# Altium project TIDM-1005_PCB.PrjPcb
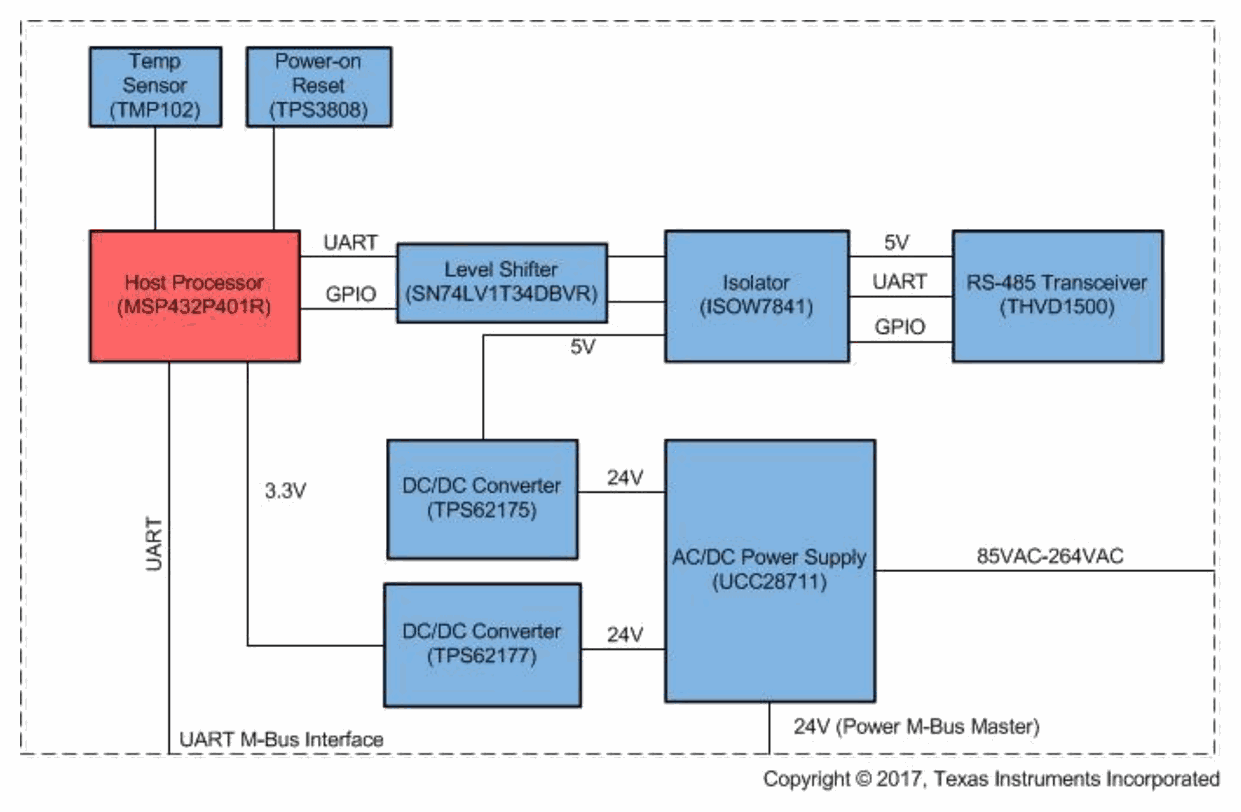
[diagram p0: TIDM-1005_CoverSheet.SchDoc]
CopyrightYear: 2017; PCB_Layout: Wonsoo Kim; PCB_Rev: E1; PRJ_Customer: Public Release; PRJ_Engineer: Wonsoo Kim; PRJ_Number: TIDM-1005; PRJ_Title: TIDM-1005; SCH_Rev: E1; TechSupport: http://www.ti.com/support; TID: TIDM-1005
5 sheets, 160 parts. Net scope: flat (ports and power ports of the same name join across sheets).
Board file: TIDM-1005_PCB.PcbDoc
Sheets:
  TIDM-1005_CoverSheet.SchDoc
  TIDM-1005_1.SchDoc
  TIDM-1005_2.SchDoc
  TIDM-1005_3.SchDoc
  TIDM-1005-EVM_Hardware.SchDoc

## Sheet TIDM-1005_CoverSheet.SchDoc
size 431 x 279 mm; Date: Not shown in title block; ApprovedBy: Not shown in title block; CheckedBy: Not shown in title block; Author: Not shown in title block; CompanyName: Not shown in title block; Engineer: Not shown in title block; Organization: Not shown in title block; Address1: Not shown in title block; Address2: Not shown in title block; Address3: Not shown in title block; Address4: Not shown in title block; DocumentNumber: 1; Revision: Use project parameter SCH_Rev; SheetNumber: 0; SheetTotal: 4; PageSetup: Record=PageOptions¦CenterHorizontal=True¦CenterVertical=True¦PrintScale=1.00¦XCorrection=1.00¦YCorrection=1.00¦PrintKind=0¦BorderSize=5000000¦LeftOffset=0¦BottomOffset=0¦Orientation=2¦PaperLength=1000¦PaperWidth=1000¦Scale=100¦PaperSource=15¦PrintQuality=600¦MediaType=1¦DitherType=10¦PaperKind=Letter¦PrintScaleMode=1

## Sheet TIDM-1005_1.SchDoc
size 431 x 279 mm; Date: Not shown in title block; ApprovedBy: Not shown in title block; CheckedBy: Not shown in title block; Author: Not shown in title block; CompanyName: Not shown in title block; Engineer: Not shown in title block; Organization: Not shown in title block; Address1: Not shown in title block; Address2: Not shown in title block; Address3: Not shown in title block; Address4: Not shown in title block; DocumentNumber: 1; Revision: Use project parameter SCH_Rev; SheetNumber: 1; SheetTotal: 4; PageSetup: Record=PageOptions¦CenterHorizontal=True¦CenterVertical=True¦PrintScale=1.00¦XCorrection=1.00¦YCorrection=1.00¦PrintKind=0¦BorderSize=5000000¦LeftOffset=0¦BottomOffset=0¦Orientation=2¦PaperLength=1000¦PaperWidth=1000¦Scale=100¦PaperSource=15¦PrintQuality=600¦MediaType=1¦DitherType=10¦PaperKind=Letter¦PrintScaleMode=1
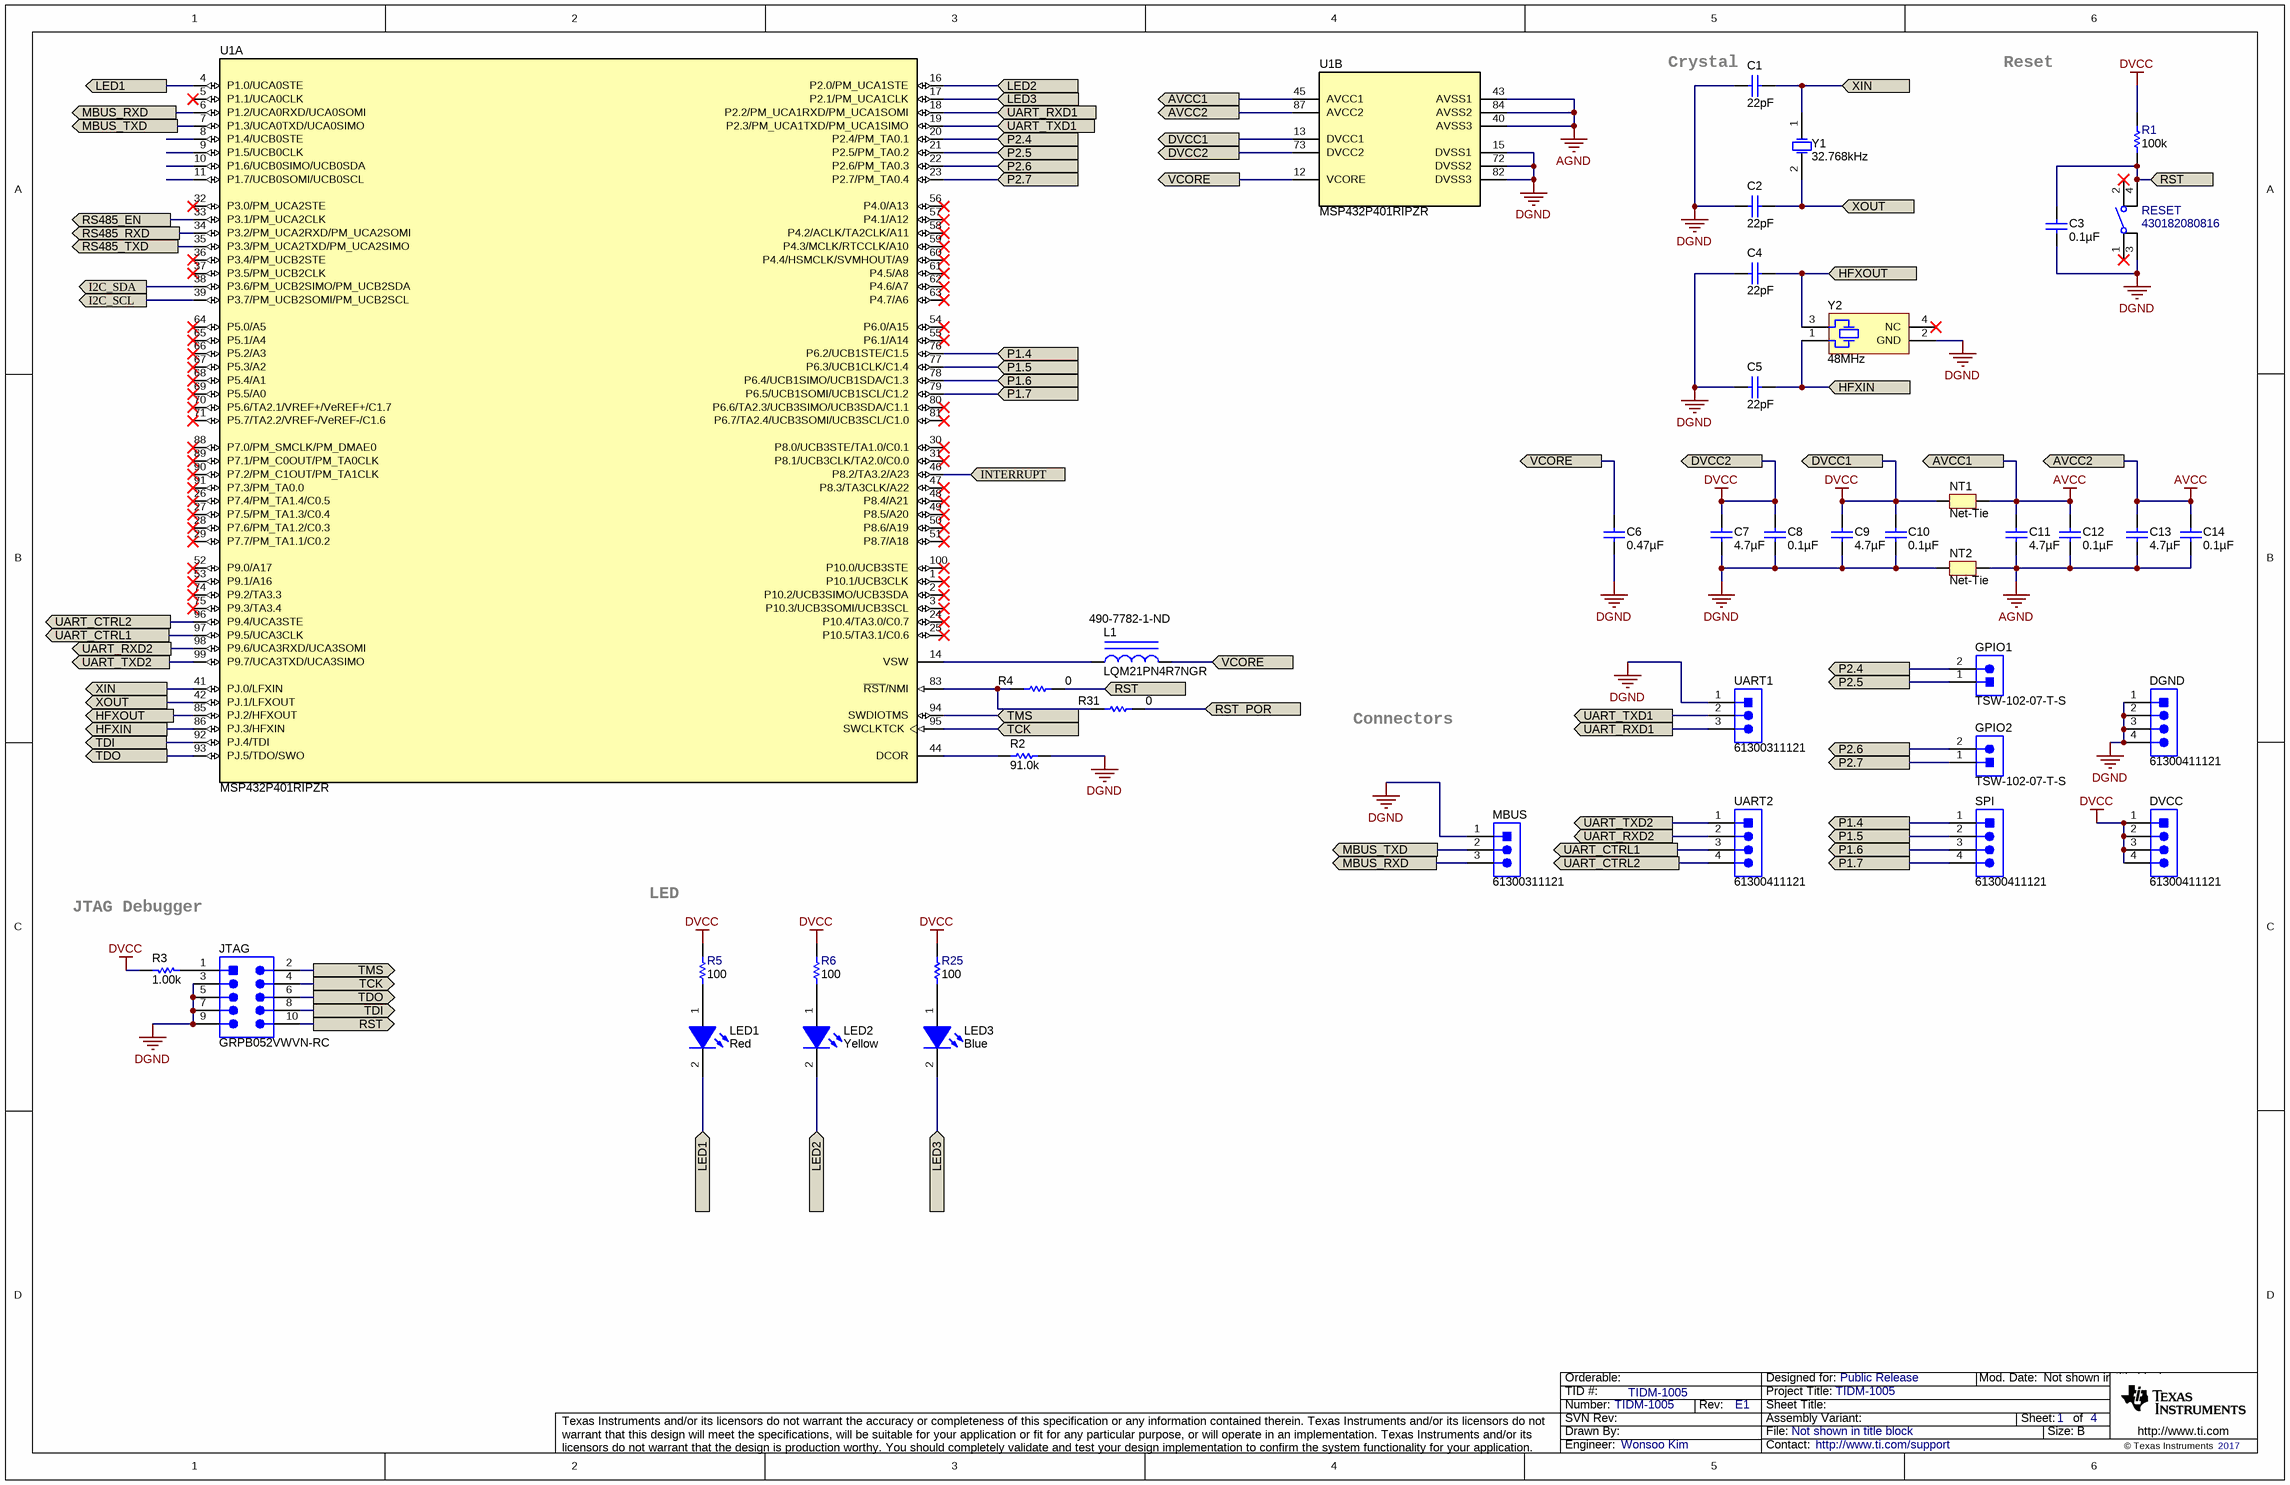
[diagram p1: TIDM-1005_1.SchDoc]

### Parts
C1  ValueDisplayed: 22pF  [0402]  (hidden comment: C1005C0G1H220J050BA)
C2  ValueDisplayed: 22pF  [0402]  (hidden comment: C1005C0G1H220J050BA)
C3  ValueDisplayed: 0.1µF  [0603]  (hidden comment: 06033C104KAT2A)
C4  ValueDisplayed: 22pF  [0402]  (hidden comment: C1005C0G1H220J050BA)
C5  ValueDisplayed: 22pF  [0402]  (hidden comment: C1005C0G1H220J050BA)
C6  ValueDisplayed: 0.47µF  [0603]  (hidden comment: GRM188R71E474KA12D)
C7  ValueDisplayed: 4.7µF  [0603]  (hidden comment: GRM188R6YA475KE15D)
C8  ValueDisplayed: 0.1µF  [0603]  (hidden comment: GCM188R71H104KA57D)
C9  ValueDisplayed: 4.7µF  [0603]  (hidden comment: GRM188R6YA475KE15D)
C10  ValueDisplayed: 0.1µF  [0603]  (hidden comment: GCM188R71H104KA57D)
C11  ValueDisplayed: 4.7µF  [0603]  (hidden comment: GRM188R6YA475KE15D)
C12  ValueDisplayed: 0.1µF  [0603]  (hidden comment: GCM188R71H104KA57D)
C13  ValueDisplayed: 4.7µF  [0603]  (hidden comment: GRM188R6YA475KE15D)
C14  ValueDisplayed: 0.1µF  [0603]  (hidden comment: GCM188R71H104KA57D)
DGND  61300411121  [WURTH_61300411121]
DVCC  61300411121  [WURTH_61300411121]
GPIO1  TSW-102-07-T-S  [Samtec_TSW-102-07-T-S]
GPIO2  TSW-102-07-T-S  [Samtec_TSW-102-07-T-S]
JTAG  GRPB052VWVN-RC  [CONN_GRPB052VWVN-RC]
L1  LQM21PN4R7NGR  Supplier Part Number 4: 490-7782-1-ND  [IND_LQM18P_FH]
LED1  value Red  [LED_LTST-C170_Red]  (hidden comment: LTST-C170KRKT)
LED2  value Yellow  [LED_LTST-C170]  (hidden comment: LTST-C170KSKT)
LED3  value Blue  [LTST-C170TBKT_Blue]  (hidden comment: LTST-C170TBKT)
MBUS  61300311121  [WURTH_61300311121]
NT1  Net-Tie  [Net-Tie_10mil]  (net tie, no BOM)
NT2  Net-Tie  [Net-Tie_10mil]  (net tie, no BOM)
R1  ValueDisplayed: 100k  [0603]  (hidden comment: ERA-3AEB104V)
R2  ValueDisplayed: 91.0k  [0805_HV]  (hidden comment: RG2012P-913-B-T5)
R3  ValueDisplayed: 1.00k  [0603]  (hidden comment: ERJ-3EKF1001V)
R4  value 0  [0603]  (hidden comment: CRCW06030000Z0EA)
R5  ValueDisplayed: 100  [0603]  (hidden comment: ERA-3AEB101V)
R6  ValueDisplayed: 100  [0603]  (hidden comment: ERA-3AEB101V)
R25  ValueDisplayed: 100  [0603]  (hidden comment: ERA-3AEB101V)
R31  value 0  [0603]  (hidden comment: CRCW06030000Z0EA)
RESET  430182080816  [SW_430182080816]
SPI  61300411121  [WURTH_61300411121]
U1  MSP432P401RIPZR  [PZ0100A_N]  (parts A,B of 2)
UART1  61300311121  [WURTH_61300311121]
UART2  61300411121  [WURTH_61300411121]
Y1  Frequency: 32.768kHz  [Epson_FC-135]  (hidden comment: FC-135R 32.7680KA-A3)
Y2  Frequency: 48MHz  [Kyocera_CX2016DB]  (hidden comment: CX2016DB48000H0FLJC1)

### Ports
AVCC1, AVCC2, DVCC1, DVCC2, HFXIN, HFXOUT, I2C_SCL, I2C_SDA, INTERRUPT, LED1, LED2, LED3, MBUS_RXD, MBUS_TXD, P1.4, P1.5, P1.6, P1.7, P2.4, P2.5, P2.6, P2.7, RS485_EN, RS485_RXD, RS485_TXD, RST, RST_POR, TCK, TDI, TDO, TMS, UART_CTRL1, UART_CTRL2, UART_RXD1, UART_RXD2, UART_TXD1, UART_TXD2, VCORE, XIN, XOUT

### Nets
AGND: C11.1 C12.2 C13.1 C14.2 NT2.2 U1.40(AVSS3) U1.43(AVSS1) U1.84(AVSS2)
AVCC: C11.2 C12.1 C13.2 C14.1 NT1.2 U1.45(AVCC1) U1.87(AVCC2) ; port AVCC1, port AVCC2
DGND: C1.1 C2.1 C3.2 C4.1 C5.1 C6.2 C7.1 C8.2 C9.1 C10.2 DGND.1 DGND.2 DGND.3 DGND.4 JTAG.3 JTAG.5 JTAG.7 JTAG.9 MBUS.1 NT2.1 R2.2 RESET.3 U1.15(DVSS1) U1.72(DVSS2) U1.82(DVSS3) UART1.1 Y2.2(GND)
DVCC: C7.2 C8.1 C9.2 C10.1 DVCC.1 DVCC.2 DVCC.3 DVCC.4 NT1.1 R1.2 R3.2 R5.2 R6.2 R25.2 U1.13(DVCC1) U1.73(DVCC2) ; port DVCC1, port DVCC2
HFXIN: C5.2 U1.86(PJ.3/HFXIN) Y2.1 ; port HFXIN
HFXOUT: C4.2 U1.85(PJ.2/HFXOUT) Y2.3 ; port HFXOUT
I2C_SCL: U1.39(P3.7/PM_UCB2SOMI/PM_UCB2SCL) ; port I2C_SCL
I2C_SDA: U1.38(P3.6/PM_UCB2SIMO/PM_UCB2SDA) ; port I2C_SDA
INTERRUPT: U1.46(P8.2/TA3.2/A23) ; port INTERRUPT
LED1: LED1.2(K) U1.4(P1.0/UCA0STE) ; port LED1
LED2: LED2.2(K) U1.16(P2.0/PM_UCA1STE) ; port LED2
LED3: LED3.2(K) U1.17(P2.1/PM_UCA1CLK) ; port LED3
MBUS_RXD: MBUS.3 U1.6(P1.2/UCA0RXD/UCA0SOMI) ; port MBUS_RXD
MBUS_TXD: MBUS.2 U1.7(P1.3/UCA0TXD/UCA0SIMO) ; port MBUS_TXD
P1.4: SPI.1 U1.76(P6.2/UCB1STE/C1.5) ; port P1.4
P1.5: SPI.2 U1.77(P6.3/UCB1CLK/C1.4) ; port P1.5
P1.6: SPI.3 U1.78(P6.4/UCB1SIMO/UCB1SDA/C1.3) ; port P1.6
P1.7: SPI.4 U1.79(P6.5/UCB1SOMI/UCB1SCL/C1.2) ; port P1.7
P2.4: GPIO1.2 U1.20(P2.4/PM_TA0.1) ; port P2.4
P2.5: GPIO1.1 U1.21(P2.5/PM_TA0.2) ; port P2.5
P2.6: GPIO2.2 U1.22(P2.6/PM_TA0.3) ; port P2.6
P2.7: GPIO2.1 U1.23(P2.7/PM_TA0.4) ; port P2.7
RS485_EN: U1.33(P3.1/PM_UCA2CLK) ; port RS485_EN
RS485_RXD: U1.34(P3.2/PM_UCA2RXD/PM_UCA2SOMI) ; port RS485_RXD
RS485_TXD: U1.35(P3.3/PM_UCA2TXD/PM_UCA2SIMO) ; port RS485_TXD
RST: C3.1 JTAG.10 R1.1 R4.1 RESET.4 ; port RST
RST_POR: R31.1 ; port RST_POR
TCK: JTAG.4 U1.95(SWCLKTCK) ; port TCK
TDI: JTAG.8 U1.92(PJ.4/TDI) ; port TDI
TDO: JTAG.6 U1.93(PJ.5/TDO/SWO) ; port TDO
TMS: JTAG.2 U1.94(SWDIOTMS) ; port TMS
UART_CTRL1: U1.97(P9.5/UCA3CLK) UART2.3 ; port UART_CTRL1
UART_CTRL2: U1.96(P9.4/UCA3STE) UART2.4 ; port UART_CTRL2
UART_RXD1: U1.18(P2.2/PM_UCA1RXD/PM_UCA1SOMI) UART1.3 ; port UART_RXD1
UART_RXD2: U1.98(P9.6/UCA3RXD/UCA3SOMI) UART2.2 ; port UART_RXD2
UART_TXD1: U1.19(P2.3/PM_UCA1TXD/PM_UCA1SIMO) UART1.2 ; port UART_TXD1
UART_TXD2: U1.99(P9.7/UCA3TXD/UCA3SIMO) UART2.1 ; port UART_TXD2
VCORE: C6.1 L1.2 U1.12(VCORE) ; port VCORE
XIN: C1.2 U1.41(PJ.0/LFXIN) Y1.1(OSC1) ; port XIN
XOUT: C2.2 U1.42(PJ.1/LFXOUT) Y1.2(OSC2) ; port XOUT
NetJTAG_1: JTAG.1 R3.1
NetL1_1: L1.1 U1.14(VSW)
NetLED1_1: LED1.1(A) R5.1
NetLED2_1: LED2.1(A) R6.1
NetLED3_1: LED3.1(A) R25.1
NetR2_1: R2.1 U1.44(DCOR)
NetR4_2: R4.2 R31.2 U1.83(~{RST}/NMI)

Not connected (* = marked no-connect by the designer): RESET 1* 2*; U1 1(P10.1/UCB3CLK)* 2(P10.2/UCB3SIMO/UCB3SDA)* 3(P10.3/UCB3SOMI/UCB3SCL)* 5(P1.1/UCA0CLK)* 8(P1.4/UCB0STE) 9(P1.5/UCB0CLK) 10(P1.6/UCB0SIMO/UCB0SDA) 11(P1.7/UCB0SOMI/UCB0SCL) 24(P10.4/TA3.0/C0.7)* 25(P10.5/TA3.1/C0.6)* 26(P7.4/PM_TA1.4/C0.5)* 27(P7.5/PM_TA1.3/C0.4)* 28(P7.6/PM_TA1.2/C0.3)* 29(P7.7/PM_TA1.1/C0.2)* 30(P8.0/UCB3STE/TA1.0/C0.1)* 31(P8.1/UCB3CLK/TA2.0/C0.0)* 32(P3.0/PM_UCA2STE)* 36(P3.4/PM_UCB2STE)* 37(P3.5/PM_UCB2CLK)* 47(P8.3/TA3CLK/A22)* 48(P8.4/A21)* 49(P8.5/A20)* 50(P8.6/A19)* 51(P8.7/A18)* 52(P9.0/A17)* 53(P9.1/A16)* 54(P6.0/A15)* 55(P6.1/A14)* 56(P4.0/A13)* 57(P4.1/A12)* 58(P4.2/ACLK/TA2CLK/A11)* 59(P4.3/MCLK/RTCCLK/A10)* 60(P4.4/HSMCLK/SVMHOUT/A9)* 61(P4.5/A8)* 62(P4.6/A7)* 63(P4.7/A6)* 64(P5.0/A5)* 65(P5.1/A4)* 66(P5.2/A3)* 67(P5.3/A2)* 68(P5.4/A1)* 69(P5.5/A0)* 70(P5.6/TA2.1/VREF+/VeREF+/C1.7)* 71(P5.7/TA2.2/VREF-/VeREF-/C1.6)* 74(P9.2/TA3.3)* 75(P9.3/TA3.4)* 80(P6.6/TA2.3/UCB3SIMO/UCB3SDA/C1.1)* 81(P6.7/TA2.4/UCB3SOMI/UCB3SCL/C1.0)* 88(P7.0/PM_SMCLK/PM_DMAE0)* 89(P7.1/PM_C0OUT/PM_TA0CLK)* 90(P7.2/PM_C1OUT/PM_TA1CLK)* 91(P7.3/PM_TA0.0)* 100(P10.0/UCB3STE)*; Y2 4(NC)*

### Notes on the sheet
- (near C1) Crystal
- Reset
- Connectors
- LED
- JTAG Debugger

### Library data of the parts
C1 C2 C4 C5 = C1005C0G1H220J050BA: CAP, CERM, 22 pF, 50 V, +/- 5%, C0G/NP0, 0402; Manufacturer: TDK; Polarized: N; CompType: Capacitor; Value: 22pF; U/M: EA; Cap_F: 0.000000000022; Tolerance_%: 5; Value1: Unknown; VDC_V: 50; Value2: 50V; TaMin_C: -55; TaMax_C: 125; SizeArea_mm2: 0.5; SizeAreaWB_mm2: 3; SizeX_mm: 1; SizeZ_mm: 0.6; AEC Category: Q200
C3 = 06033C104KAT2A: CAP, CERM, 0.1 µF, 25 V, +/- 10%, X7R, 0603; Manufacturer: AVX; Polarized: N; CompType: Capacitor; Value: 0.1uF; U/M: EA; Cap_F: 0.0000001; Tolerance_%: 10; ESR_ohm: 0.05; Value1: 0.05 ohm; VDC_V: 25; Value2: 25V; TaMin_C: -55; TaMax_C: 125
C6 = GRM188R71E474KA12D: CAP, CERM, 0.47 µF, 25 V, +/- 10%, X7R, 0603; Manufacturer: MuRata; Polarized: N; CompType: Capacitor; Value: 0.47uF; U/M: EA; Cap_F: 0.00000047; Tolerance_%: 10; Value1: Unknown; VDC_V: 25; Value2: 25V; TaMin_C: -55; TaMax_C: 125
C7 C9 C11 C13 = GRM188R6YA475KE15D: CAP, CERM, 4.7 µF, 35 V, +/- 10%, X5R, 0603; Manufacturer: MuRata; Polarized: N; CompType: Capacitor; Value: 4.7uF; U/M: EA; Cap_F: 0.0000047; Tolerance_%: 10; Value1: Unknown; VDC_V: 35; Value2: 35V; TaMin_C: -55; TaMax_C: 85; SizeArea_mm2: 1.28; SizeAreaWB_mm2: 4.68; SizeX_mm: 1.6; SizeY_mm: 0.8; SizeZ_mm: 1; AEC Category: Q200
C8 C10 C12 C14 = GCM188R71H104KA57D: CAP, CERM, 0.1 µF, 50 V, +/- 10%, X7R, 0603; Manufacturer: MuRata; Polarized: N; CompType: Capacitor; Value: 0.1uF; U/M: EA; Cap_F: 0.0000001; Tolerance_%: 10; ESR_ohm: 0.02; Value1: 0.02 ohm; VDC_V: 50; Value2: 50V; IRMS_A: 1.84; TaMin_C: -55; TaMax_C: 125
DGND DVCC = 61300411121: Header, 2.54 mm, 4x1, Gold, TH; Manufacturer: Wurth Elektronik; SymbolCreator: a0412235; U/M: EA
GPIO1 GPIO2 = TSW-102-07-T-S: Header, 2.54 mm, 2x1, Tin, TH; Manufacturer: Samtec; SymbolCreator: a0412235; Pitch_mm: 2.54; Gender: Male; Shrouded: N; Row_Count: 1; Current_A: 6.3; Voltage_V: 550; Cert_CSA: Y
JTAG = GRPB052VWVN-RC: Header, 50mil, 5x2, Gold, TH; Manufacturer: Sullins Connector Solutions; SymbolCreator: a0412235; U/M: EA
L1 = LQM21PN1R0MGH: Inductor, Multilayer, Ferrite, 4.7 µH, 2 A, 0.08 ohm, SMD; Manufacturer: MuRata; Value: 4.7uH; Ind_H: 1.0E-6; Imax_A: 2; Irms: 2A @ 40C rise; Isat: 2.1A @ 30% inductance drop; DCR_ohm: 0.08; Value2: 2A; Tolerance_%: ±30%; Current Rating: 800mA; Shielding: Shielded; Frequency - Self Resonant: 30MHz; Frequency - Test: 1MHz
LED1 = LTST-C170KRKT: LED, Red, SMD; Manufacturer: Lite-On; Type: AlInGaP; Vf_V: 2; Value2: 2V; Io_A: 0.02; Value1: W; SizeAreaWB_mm2: 6.75; SizeArea_mm2: 2.5; SizeY_mm: 1.25; SizeZ_mm: 1.2; U/M: EA
LED2 = LTST-C170KSKT: LED, Yellow , SMD; Manufacturer: Lite-On; Type: AlInGaP; Vf_V: 2; Value2: 2V; Io_A: 0.02; Value1: W; SizeAreaWB_mm2: 6.75; SizeArea_mm2: 2.5; SizeY_mm: 1.25; SizeZ_mm: 1.2; U/M: EA
LED3 = LTST-C170TBKT: LED, Blue, SMD; Manufacturer: Lite-On; Type: AlInGaP; Vf_V: 3.3; Value2: 3.3V; Io_A: 0.02; Value1: W; U/M: EA
MBUS UART1 = 61300311121: Header, 2.54 mm, 3x1, Gold, TH; Manufacturer: Wurth Elektronik; SymbolCreator: a0799628
NT1 NT2 = Net-Tie: Single point connection between nets.; SymbolCreator: codlsc
R1 = ERA-3AEB104V: RES, 100 k, 0.1%, 0.1 W, 0603; Manufacturer: Panasonic; CompType: Resistor; Value: 100k; Res_ohm: 100000; Tolerance_%: 0.1; Value2: 0.1W; VDC_V: 75; TempCo: 25 ppm/C; EIA_Code: E192; U/M: EA
R2 = RG2012P-913-B-T5: RES, 91.0 k, 0.1%, 0.125 W, 0805; Manufacturer: Susumu Co Ltd; CompType: Resistor; Value: 91.0k; Res_ohm: 91000; Value_Code: 91k0; Tolerance_%: 0.1; Power_W: 0.125; Value2: 0.125W; VDC_V: 100; TempCo: 25 ppm/C; U/M: EA
R3 = ERJ-3EKF1001V: RES, 1.00 k, 1%, 0.1 W, 0603; Manufacturer: Panasonic; CompType: Resistor; Value: 1.00k; Res_ohm: 1000; Value_Code: 1k00; Tolerance_%: 1; Power_W: 0.1; Value2: 0.1W; VDC_V: 75; TempCo: 100 ppm/C; EIA_Code: E96; U/M: EA
R4 R31 = CRCW06030000Z0EA: RES, 0 ohm, 5%, 0.1W, 0603; Manufacturer: Vishay-Dale; CompType: Resistor; Value_Code: 0000; Tolerance_%: 5; Power_W: 0.1; VDC_V: 75; TempCo: 200 ppm/C; EIA_Code: E24; U/M: EA
R5 R6 R25 = ERA-3AEB101V: RES, 100, 0.1%, 0.1 W, 0603; Manufacturer: Panasonic; CompType: Resistor; Value: 100; Value_Code: 100R; Tolerance_%: 0.1; Value2: 0.1W; VDC_V: 75; TempCo: 25 ppm/C; EIA_Code: E192; U/M: EA
RESET = 430182080816: Switch, Tactile, SPST-NO, 0.05A, 12V, SMD; Manufacturer: Wurth Elektronik; SymbolCreator: Altium; VDC_V: 12; SwitchFunction: Off-Mom; PositionCount: 1; CurrentRating_mA: 50
SPI UART2 = 61300411121: Header, 2.54 mm, 4x1, Gold, TH; Manufacturer: Wurth Elektronik; SymbolCreator: a0412235
U1 = MSP432P401RIPZR: Mixed-Signal Microcontroller, PZ0100A (LQFP-100); Manufacturer: Texas Instruments; SymbolCreator: Altium; SizeArea_mm2: 256; SizeAreaWB_mm2: 324; SizeX_mm: 16; SizeZ_mm: 1.6; CompType: IC; U/M: EA
Y1 = X1A0001410014: Crystal, 32.768 KHz, 12.5 pF, SMD; Manufacturer: Epson; SymbolCreator: a0412235; U/M: EA; TaMin_C: -40; TaMax_C: 85
Y2 = CX2016DB48000H0FLJC1: Crystal, 48MHz, 12pF, SMD; Manufacturer: Kyocera; SymbolCreator: Altium; SizeAreaWB_mm2: 7.8; SizeArea_mm2: 3.2; SizeX_mm: 1.6; SizeY_mm: 2; SizeZ_mm: 0.45; U/M: EA; TaMin_C: -30; TaMax_C: 85; Frequency Stability: ±15ppm

## Sheet TIDM-1005_2.SchDoc
size 431 x 279 mm; Date: Not shown in title block; ApprovedBy: Not shown in title block; CheckedBy: Not shown in title block; Author: Not shown in title block; CompanyName: Not shown in title block; Engineer: Not shown in title block; Organization: Not shown in title block; Address1: Not shown in title block; Address2: Not shown in title block; Address3: Not shown in title block; Address4: Not shown in title block; DocumentNumber: 2; Revision: Use project parameter SCH_Rev; SheetNumber: 2; SheetTotal: 4; PageSetup: Record=PageOptions¦CenterHorizontal=True¦CenterVertical=True¦PrintScale=1.00¦XCorrection=1.00¦YCorrection=1.00¦PrintKind=0¦BorderSize=5000000¦LeftOffset=0¦BottomOffset=0¦Orientation=2¦PaperLength=1000¦PaperWidth=1000¦Scale=100¦PaperSource=15¦PrintQuality=600¦MediaType=1¦DitherType=10¦PaperKind=Letter¦PrintScaleMode=1
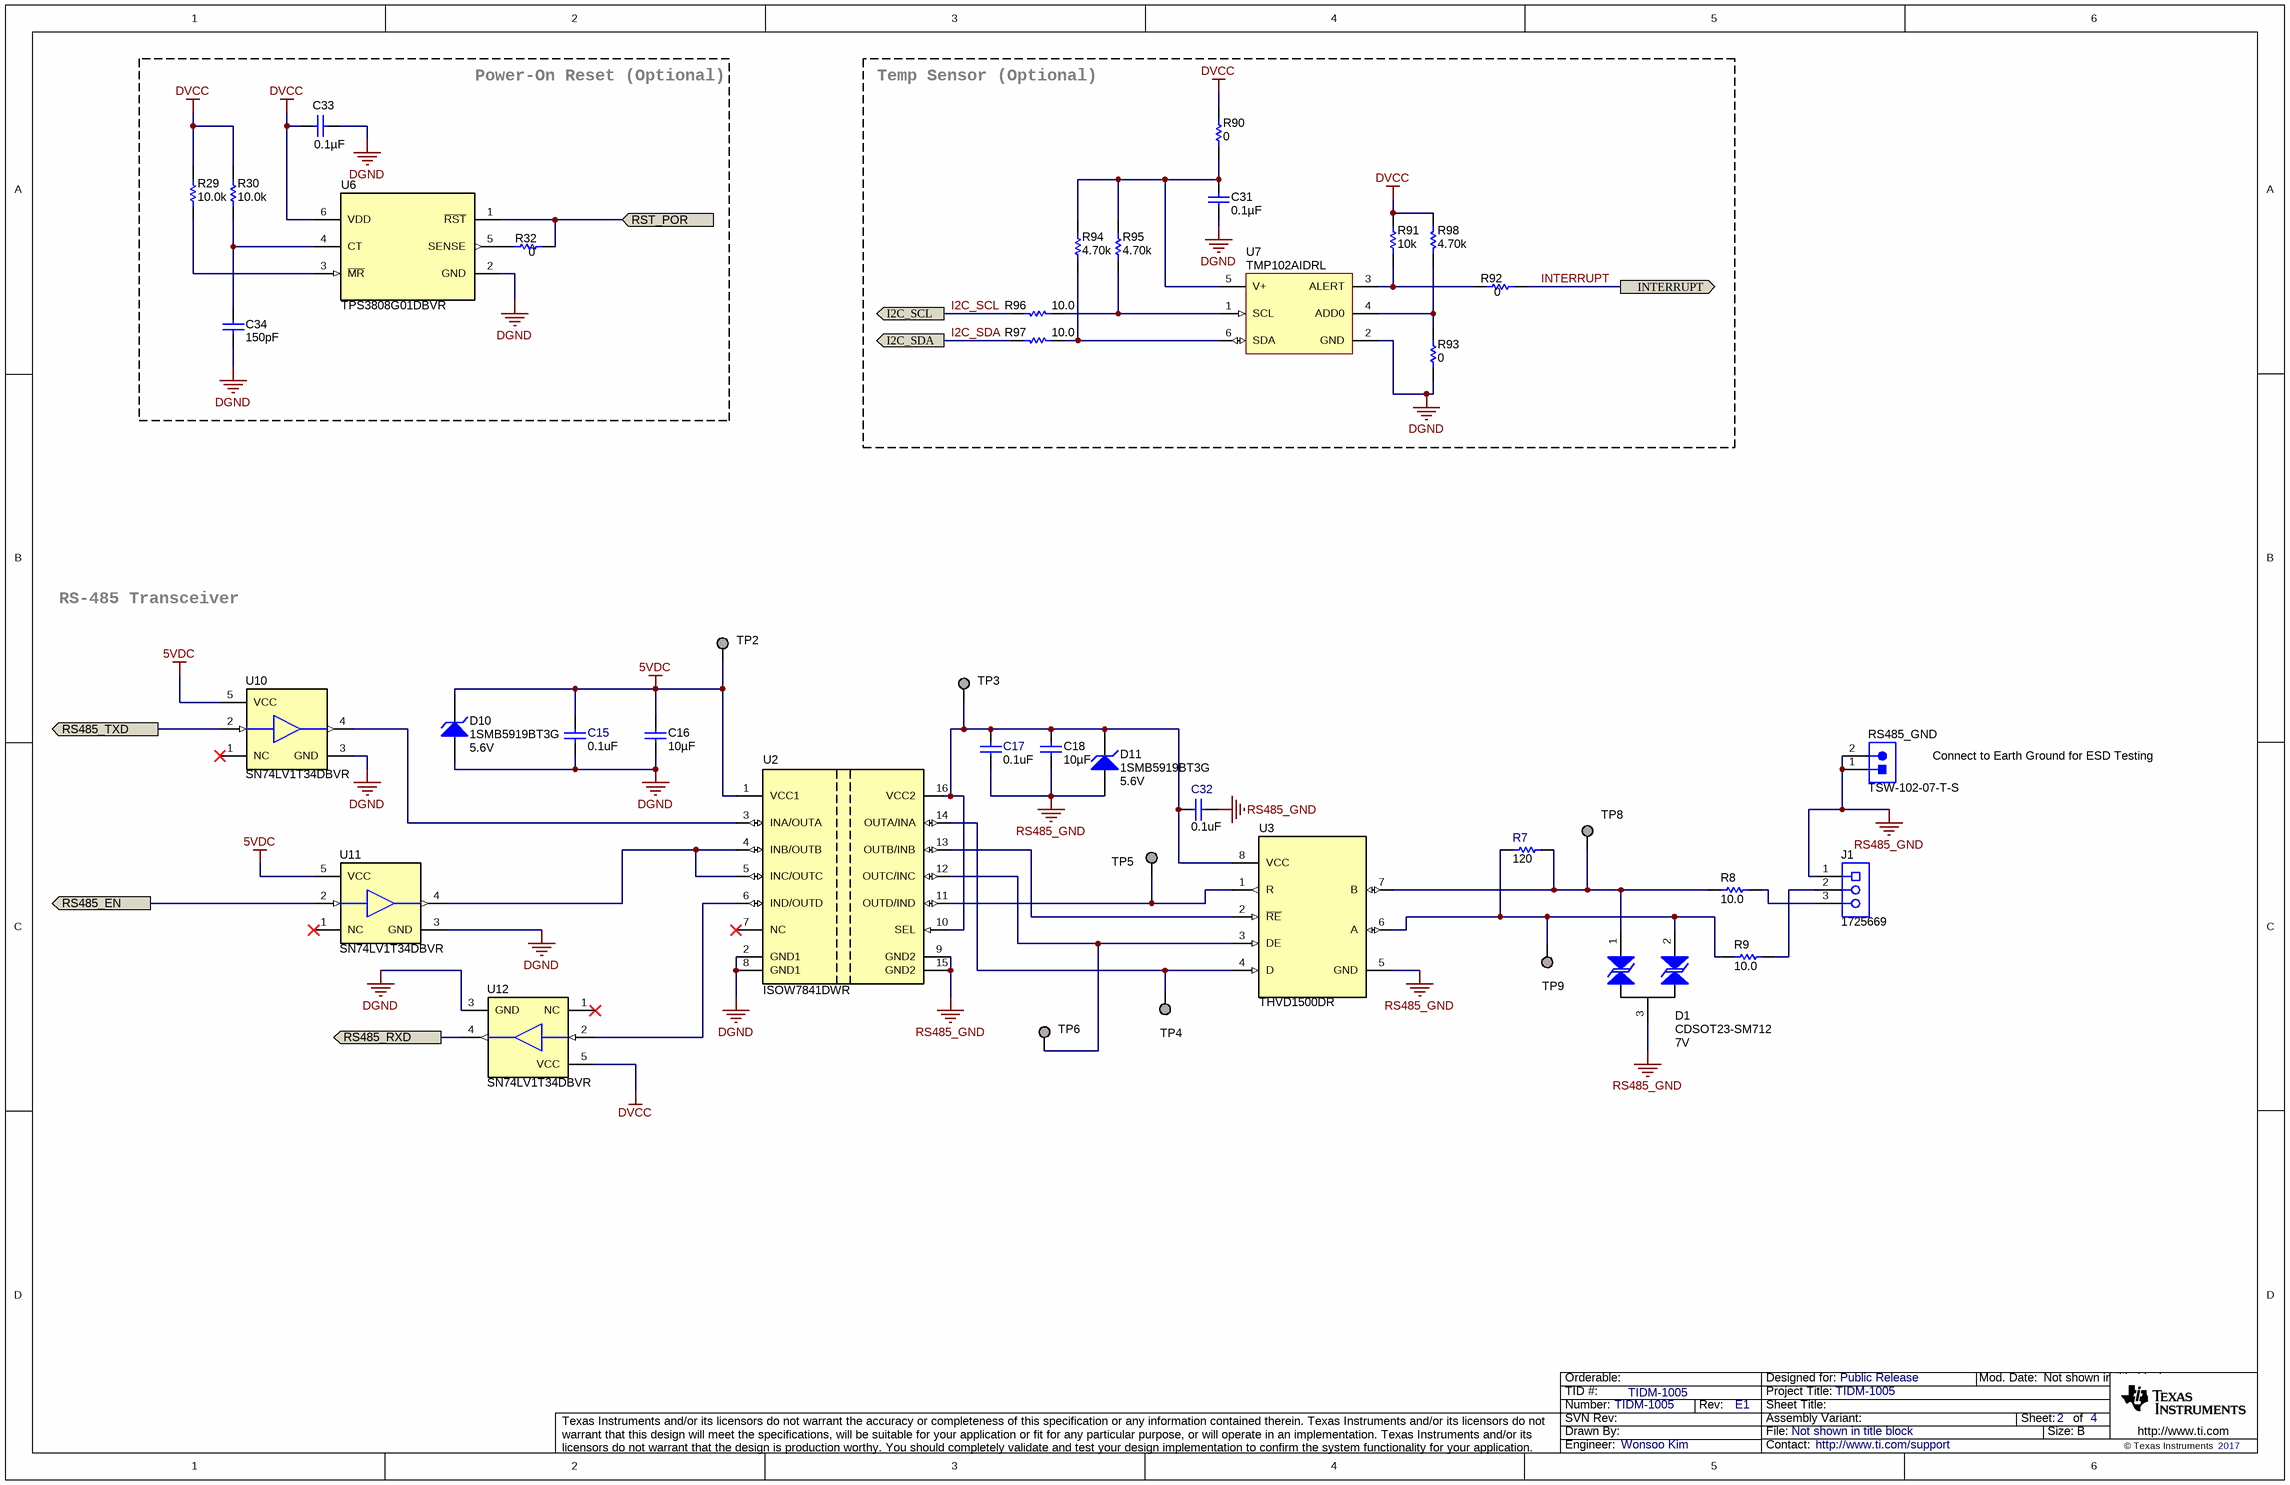
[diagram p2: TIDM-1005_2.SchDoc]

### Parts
C15  value 0.1uF  [0603]  (hidden comment: C0603C104J4RACTU)
C16  ValueDisplayed: 10µF  [0603]  (hidden comment: C0603C106M9PACTU)
C17  value 0.1uF  [0603]  (hidden comment: C0603C104J4RACTU)
C18  ValueDisplayed: 10µF  [0603]  (hidden comment: C0603C106M9PACTU)
C31  ValueDisplayed: 0.1µF  [0603]  (hidden comment: 06033C104JAT2A)
C32  value 0.1uF  [0603]  (hidden comment: C0603C104J4RACTU)
C33  ValueDisplayed: 0.1µF  [0603M]  (hidden comment: 06033C104JAT2A)
C34  ValueDisplayed: 150pF  [0603]  (hidden comment: 06035A151JAT2A)
D1  CDSOT23-SM712  value 7V  [SOT-23]
D10  1SMB5919BT3G  value 5.6V  [SMB]
D11  1SMB5919BT3G  value 5.6V  [SMB]
J1  1725669  [Phoenix_1725669]
R7  value 120  [0603]  (hidden comment: CRCW0603120RJNEA)
R8  ValueDisplayed: 10.0  [2512]  (hidden comment: CRCW251210R0FKEG)
R9  ValueDisplayed: 10.0  [2512]  (hidden comment: CRCW251210R0FKEG)
R29  value 10.0k  [0402M]  (hidden comment: CRCW040210K0FKED)
R30  value 10.0k  [0402M]  (hidden comment: CRCW040210K0FKED)
R32  value 0  [0603]  (hidden comment: CRCW06030000Z0EA)
R90  ValueDisplayed: 0  [0603]  (hidden comment: RC0603JR-070RL)
R91  ValueDisplayed: 10k  [0603]  (hidden comment: CRCW060310K0JNEA)
R92  ValueDisplayed: 0  [0603]  (hidden comment: RC0603JR-070RL)
R93  ValueDisplayed: 0  [0603]  (hidden comment: RC0603JR-070RL)
R94  ValueDisplayed: 4.70k  [0603]  (hidden comment: RC0603FR-074K7L)
R95  ValueDisplayed: 4.70k  [0603]  (hidden comment: RC0603FR-074K7L)
R96  ValueDisplayed: 10.0  [0603]  (hidden comment: CRCW060310R0FKEA)
R97  ValueDisplayed: 10.0  [0603]  (hidden comment: CRCW060310R0FKEA)
R98  ValueDisplayed: 4.70k  [0603]  (hidden comment: RC0603FR-074K7L)
RS485_GND  TSW-102-07-T-S  [Samtec_TSW-102-07-T-S]
TP2  TESTPOINT  [TESTPOINT]  (value not drawn)  (no BOM)
TP3  TESTPOINT  [TESTPOINT]  (value not drawn)  (no BOM)
TP4  TESTPOINT  [TESTPOINT]  (value not drawn)  (no BOM)
TP5  TESTPOINT  [TESTPOINT]  (value not drawn)  (no BOM)
TP6  TESTPOINT  [TESTPOINT]  (value not drawn)  (no BOM)
TP8  TESTPOINT  [TESTPOINT]  (value not drawn)  (no BOM)
TP9  TESTPOINT  [TESTPOINT]  (value not drawn)  (no BOM)
U2  ISOW7841DWR  [DW0016B_N]
U3  THVD1500DR  [D0008A_N]
U6  TPS3808G01DBVR  [DBV0006A_N]
U7  TMP102AIDRL  [DRL0006A_N]
U10  SN74LV1T34DBVR  [DBV0005A_N]
U11  SN74LV1T34DBVR  [DBV0005A_N]
U12  SN74LV1T34DBVR  [DBV0005A_N]

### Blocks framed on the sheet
Power-On Reset (Optional): C33 C34 R29 R30 R32 U6
Temp Sensor (Optional): C31 R90-R98 U7

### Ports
I2C_SCL, I2C_SDA, INTERRUPT (out), RS485_EN, RS485_RXD, RS485_TXD, RST_POR

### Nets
5VDC: C15.1 C16.2 D10.1(K) TP2.1 U2.1(VCC1) U10.5(VCC) U11.5(VCC)
DGND: C15.2 C16.1 C31.1 C33.1 C34.2 D10.2(A) R93.2 U2.2(GND1) U2.8(GND1) U6.2(GND) U7.2(GND) U10.3(GND) U11.3(GND) U12.3(GND)
DVCC: C33.2 R29.2 R30.2 R90.2 R91.2 R98.2 U6.6(VDD) U12.5(VCC)
RS485_GND: C17.2 C18.1 C32.2 D1.3 D11.2(A) J1.1 RS485_GND.1 RS485_GND.2 U2.9(GND2) U2.15(GND2) U3.5(GND)
I2C_SCL: R96.2 ; port I2C_SCL
I2C_SDA: R97.2 ; port I2C_SDA
INTERRUPT: R92.2 ; port INTERRUPT
RS485_EN: U11.2(A) ; port RS485_EN
RS485_RXD: U12.4(Y) ; port RS485_RXD
RS485_TXD: U10.2(A) ; port RS485_TXD
RST_POR: R32.1 U6.1(~{RST}) ; port RST_POR
NetC17_1: C17.1 C18.2 C32.1 D11.1(K) TP3.1 U2.10(SEL) U2.16(VCC2) U3.8(VCC)
NetC31_2: C31.2 R90.1 R94.2 R95.2 U7.5(V+)
NetC34_1: C34.1 R30.1 U6.4(CT)
NetD1_1: D1.1 R7.1 R8.1 TP8.1 U3.7(B)
NetD1_2: D1.2 R7.2 R9.1 TP9.1 U3.6(A)
NetJ1_2: J1.2 R9.2
NetJ1_3: J1.3 R8.2
NetR29_1: R29.1 U6.3(~{MR})
NetR32_2: R32.2 U6.5(SENSE)
NetR91_1: R91.1 R92.1 U7.3(ALERT)
NetR93_1: R93.1 R98.1 U7.4(ADD0)
NetR94_1: R94.1 R97.1 U7.6(SDA)
NetR95_1: R95.1 R96.1 U7.1(SCL)
NetTP4_1: TP4.1 U2.14(OUTA/INA) U3.4(D)
NetTP5_1: TP5.1 U2.11(OUTD/IND) U3.1(R)
NetTP6_1: TP6.1 U2.12(OUTC/INC) U3.3(DE)
NetU2_3: U2.3(INA/OUTA) U10.4(Y)
NetU2_4: U2.4(INB/OUTB) U2.5(INC/OUTC) U11.4(Y)
NetU2_6: U2.6(IND/OUTD) U12.2(A)
NetU2_13: U2.13(OUTB/INB) U3.2(~{RE})

Not connected (* = marked no-connect by the designer): U2 7(NC)*; U10 1(NC)*; U11 1(NC)*; U12 1(NC)*

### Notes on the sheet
- RS-485 Transceiver
- Connect to Earth Ground for ESD Testing

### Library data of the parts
C15 C17 C32 = C0603C104J4RACTU: CAP, CERM, 0.1uF, 16V, +/-5%, X7R, 0603; Manufacturer: Kemet; Polarized: N; CompType: Capacitor; ValueDisplayed: 0.1µF; U/M: EA; Cap_F: 0.0000001; Tolerance_%: 5; Value1: Unknown; VDC_V: 16; TaMin_C: -55; TaMax_C: 125
C16 C18 = C0603C106M9PACTU: CAP, CERM, 10 µF, 6.3 V, +/- 20%, X5R, 0603; Manufacturer: Kemet; Polarized: N; CompType: Capacitor; Value: 10uF; U/M: EA; Cap_F: 0.00001; Tolerance_%: 20; ESR_ohm: 0.004; Value1: 0.004 ohm; VDC_V: 6.3; Value2: 6.3V; IRMS_A: 8.9; TaMin_C: -55; TaMax_C: 85; SizeArea_mm2: 1.28; SizeAreaWB_mm2: 4.68; SizeX_mm: 1.6; SizeY_mm: 0.8; SizeZ_mm: 1; AEC Category: Q200
C31 = 06033C104JAT2A: CAP, CERM, 0.1 µF, 25 V, +/- 5%, X7R, 0603; Manufacturer: AVX; Polarized: N; CompType: Capacitor; Value: 0.1uF; U/M: EA; Cap_F: 0.0000001; Tolerance_%: 5; ESR_ohm: 0.05; Value1: 0.05 ohm; VDC_V: 25; Value2: 25V; TaMin_C: -55; TaMax_C: 125; AEC Category: Q200
C33 = 06033C104JAT2A: CAP, CERM, 0.1uF, 25V, +/-5%, X7R, 0603; Manufacturer: AVX; Polarized: N; CompType: Capacitor; U/M: EA; Cap_F: 0.0000001; Tolerance_%: 5; ESR_Ohm: 0.05; Value1: 0.05 ohm; VDC_V: 25; TaMin_C: -55; TaMax_C: 125; Cap_Case: 0603
C34 = 06035A151JAT2A: CAP, CERM, 150 pF, 50 V, +/- 5%, C0G/NP0, 0603; Manufacturer: AVX; Polarized: N; CompType: Capacitor; Value: 150pF; U/M: EA; Cap_F: 0.00000000015; Tolerance_%: 5; ESR_ohm: 0.098; Value1: 0.098 ohm; VDC_V: 50; Value2: 50V; TaMin_C: -55; TaMax_C: 125; SizeArea_mm2: 1.28; SizeAreaWB_mm2: 4.68; SizeX_mm: 1.6; SizeY_mm: 0.8; SizeZ_mm: 1; AEC Category: Q200
D1 = CDSOT23-SM712: Diode, TVS, Bi, 7 V, SOT-23; Manufacturer: Bourns; SymbolCreator: a0411947; U/M: EA; Vr_V: 7; Value1: W; SizeAreaWB_mm2: 14; SizeArea_mm2: 7.5; SizeX_mm: 2.5; SizeY_mm: 3; SizeZ_mm: 1.1; AEC Category: Q101
D10 D11 = 1SMB5919BT3G: Diode, Zener, 5.6 V, 550 mW, SMB; Manufacturer: ON Semiconductor; SymbolCreator: a0412235; U/M: EA; Power_W: 0.55; Vz_V: 5.6; Value1: 0.55W; RJA_CperW: 226; SizeAreaWB_mm2: 44.156; SizeArea_mm2: 21.336; SizeY_mm: 3.81; SizeZ_mm: 2.6; AEC Category: Q101
J1 = 1725669: Terminal Block, 3x1, 2.54 mm, TH; Manufacturer: Phoenix Contact; SymbolCreator: a0412235
R7 = CRCW0603120RJNEA: RES, 120 ohm, 5%, 0.1W, 0603; Manufacturer: Vishay-Dale; CompType: Resistor; Value_Code: 120R; Tolerance_%: 5; Power_W: 0.1; VDC_V: 75; TempCo: 200 ppm/C; EIA_Code: E24; U/M: EA
R8 R9 = CRCW251210R0FKEG: RES, 10.0, 1%, 1 W, AEC-Q200 Grade 0, 2512; Manufacturer: Vishay-Dale; CompType: Resistor; Value: 10.0; Res_ohm: 10; Value_Code: 10R0; Tolerance_%: 1; Value2: 1W; VDC_V: 500; TempCo: 100 ppm/C; SizeArea_mm2: 20.16; SizeX_mm: 6.3; SizeY_mm: 3.2; SizeZ_mm: 0.71; EIA_Code: E96; U/M: EA; AEC Category: Q200; AEC Qualified: Y; AEC Grade: 0
R29 R30 = CRCW040210K0FKED: RES, 10.0k ohm, 1%, 0.063W, 0402; Manufacturer: Vishay-Dale; CompType: Resistor; Res_ohm: 10000; Value_Code: 10k0; Tolerance_%: 1; Power_W: 0.063; VDC_V: 50; TempCo: 100 ppm/C; EIA_Code: E96; U/M: EA
R32 = CRCW06030000Z0EA: as R4 on sheet TIDM-1005_1
R90 R92 R93 = RC0603JR-070RL: RES, 0, 5%, 0.1 W, 0603; Manufacturer: Yageo America; CompType: Resistor; Value: 0; Value_Code: 0000; Tolerance_%: 5; Power_W: 0.1; Value2: 0.1W; VDC_V: 50; TempCo: 200 ppm/C; EIA_Code: E24; U/M: EA; AEC Category: Q200
R91 = CRCW060310K0JNEA: RES, 10 k, 5%, 0.1 W, 0603; Manufacturer: Vishay-Dale; CompType: Resistor; Value: 10k; Res_ohm: 10000; Value_Code: 10k0; Tolerance_%: 5; Power_W: 0.1; Value2: 0.1W; VDC_V: 75; TempCo: 200 ppm/C; SizeArea_mm2: 1.28; SizeX_mm: 1.6; SizeY_mm: 0.8; SizeZ_mm: 1; EIA_Code: E24; U/M: EA; AEC Category: Q200
R94 R95 R98 = RC0603FR-074K7L: RES, 4.70 k, 1%, 0.1 W, 0603; Manufacturer: Yageo America; CompType: Resistor; Value: 4.70k; Res_ohm: 4700; Value_Code: 4k70; Tolerance_%: 1; Power_W: 0.1; Value2: 0.1W; VDC_V: 150; TempCo: 200 ppm/C; U/M: EA; AEC Category: Q200
R96 R97 = CRCW060310R0FKEA: RES, 10.0, 1%, 0.1 W, 0603; Manufacturer: Vishay-Dale; CompType: Resistor; Value: 10.0; Res_ohm: 10; Value_Code: 10R0; Tolerance_%: 1; Power_W: 0.1; Value2: 0.1W; VDC_V: 75; TempCo: 100 ppm/C; SizeArea_mm2: 1.28; SizeX_mm: 1.6; SizeY_mm: 0.8; EIA_Code: E96; U/M: EA; AEC Category: Q200
RS485_GND = TSW-102-07-T-S: as GPIO1 on sheet TIDM-1005_1
TP2-TP6 TP8 TP9 = TESTPOINT: TEST POINT.  No entry in BOM.
U2 = ISOW7841DWR: ISOW7841DW, DW0016B (SOIC-16); Manufacturer: Texas Instruments; SymbolCreator: a0411947; SizeArea_mm2: 107.12; SizeAreaWB_mm2: 152.52; SizeX_mm: 10.4; SizeY_mm: 10.3; SizeZ_mm: 2.65; CompType: IC; U/M: EA
U3 = THVD1500DR: 250 kbps RS-485 Transceivers With ±12-kV IEC ESD Protection, D0008A (SOIC-8); Manufacturer: Texas Instruments; SymbolCreator: a0411947; SizeArea_mm2: 30.38; SizeAreaWB_mm2: 56.58; SizeX_mm: 4.9; SizeY_mm: 6.2; SizeZ_mm: 1.75; CompType: IC; U/M: EA
U6 = TPS3808G01DBVR: Low Quiescent Current, Programmable-Delay Supervisory Circuit, DBV0006A (SOT-6); Alternate PartNumber: TPS3808G01DBVT; Manufacturer: Texas Instruments; SymbolCreator: Altium; SizeArea_mm2: 8.12; SizeAreaWB_mm2: 14.82; SizeX_mm: 2.8; SizeY_mm: 2.9; SizeZ_mm: 1.45; CompType: IC; U/M: EA
U7 = TMP102AIDRL: Low Power Digital Temperature Sensor With SMBus/Two-Wire Serial Interface in SOT563, DRL0006A; Alternate Manufacturer: None; Manufacturer: Texas Instruments; SymbolCreator: a0411947; CompType: IC; U/M: EA
U10-U12 = SN74LV1T34DBVR: Single Power Supply BUFFER Logic Level Shifter (no enable), DBV0005A (SOT-5); Manufacturer: Texas Instruments; SymbolCreator: Altium; SizeArea_mm2: 8.12; SizeAreaWB_mm2: 14.82; SizeX_mm: 2.8; SizeY_mm: 2.9; SizeZ_mm: 1.45; CompType: IC; U/M: EA

## Sheet TIDM-1005_3.SchDoc
size 431 x 279 mm; Date: Not shown in title block; ApprovedBy: Not shown in title block; CheckedBy: Not shown in title block; Author: Not shown in title block; CompanyName: Not shown in title block; Engineer: Not shown in title block; Organization: Not shown in title block; Address1: Not shown in title block; Address2: Not shown in title block; Address3: Not shown in title block; Address4: Not shown in title block; DocumentNumber: 1; Revision: Use project parameter SCH_Rev; SheetNumber: 3; SheetTotal: 4; PageSetup: Record=PageOptions¦CenterHorizontal=True¦CenterVertical=True¦PrintScale=1.00¦XCorrection=1.00¦YCorrection=1.00¦PrintKind=0¦BorderSize=5000000¦LeftOffset=0¦BottomOffset=0¦Orientation=2¦PaperLength=1000¦PaperWidth=1000¦Scale=100¦PaperSource=15¦PrintQuality=600¦MediaType=1¦DitherType=10¦PrintScaleMode=1¦PaperKind=Letter
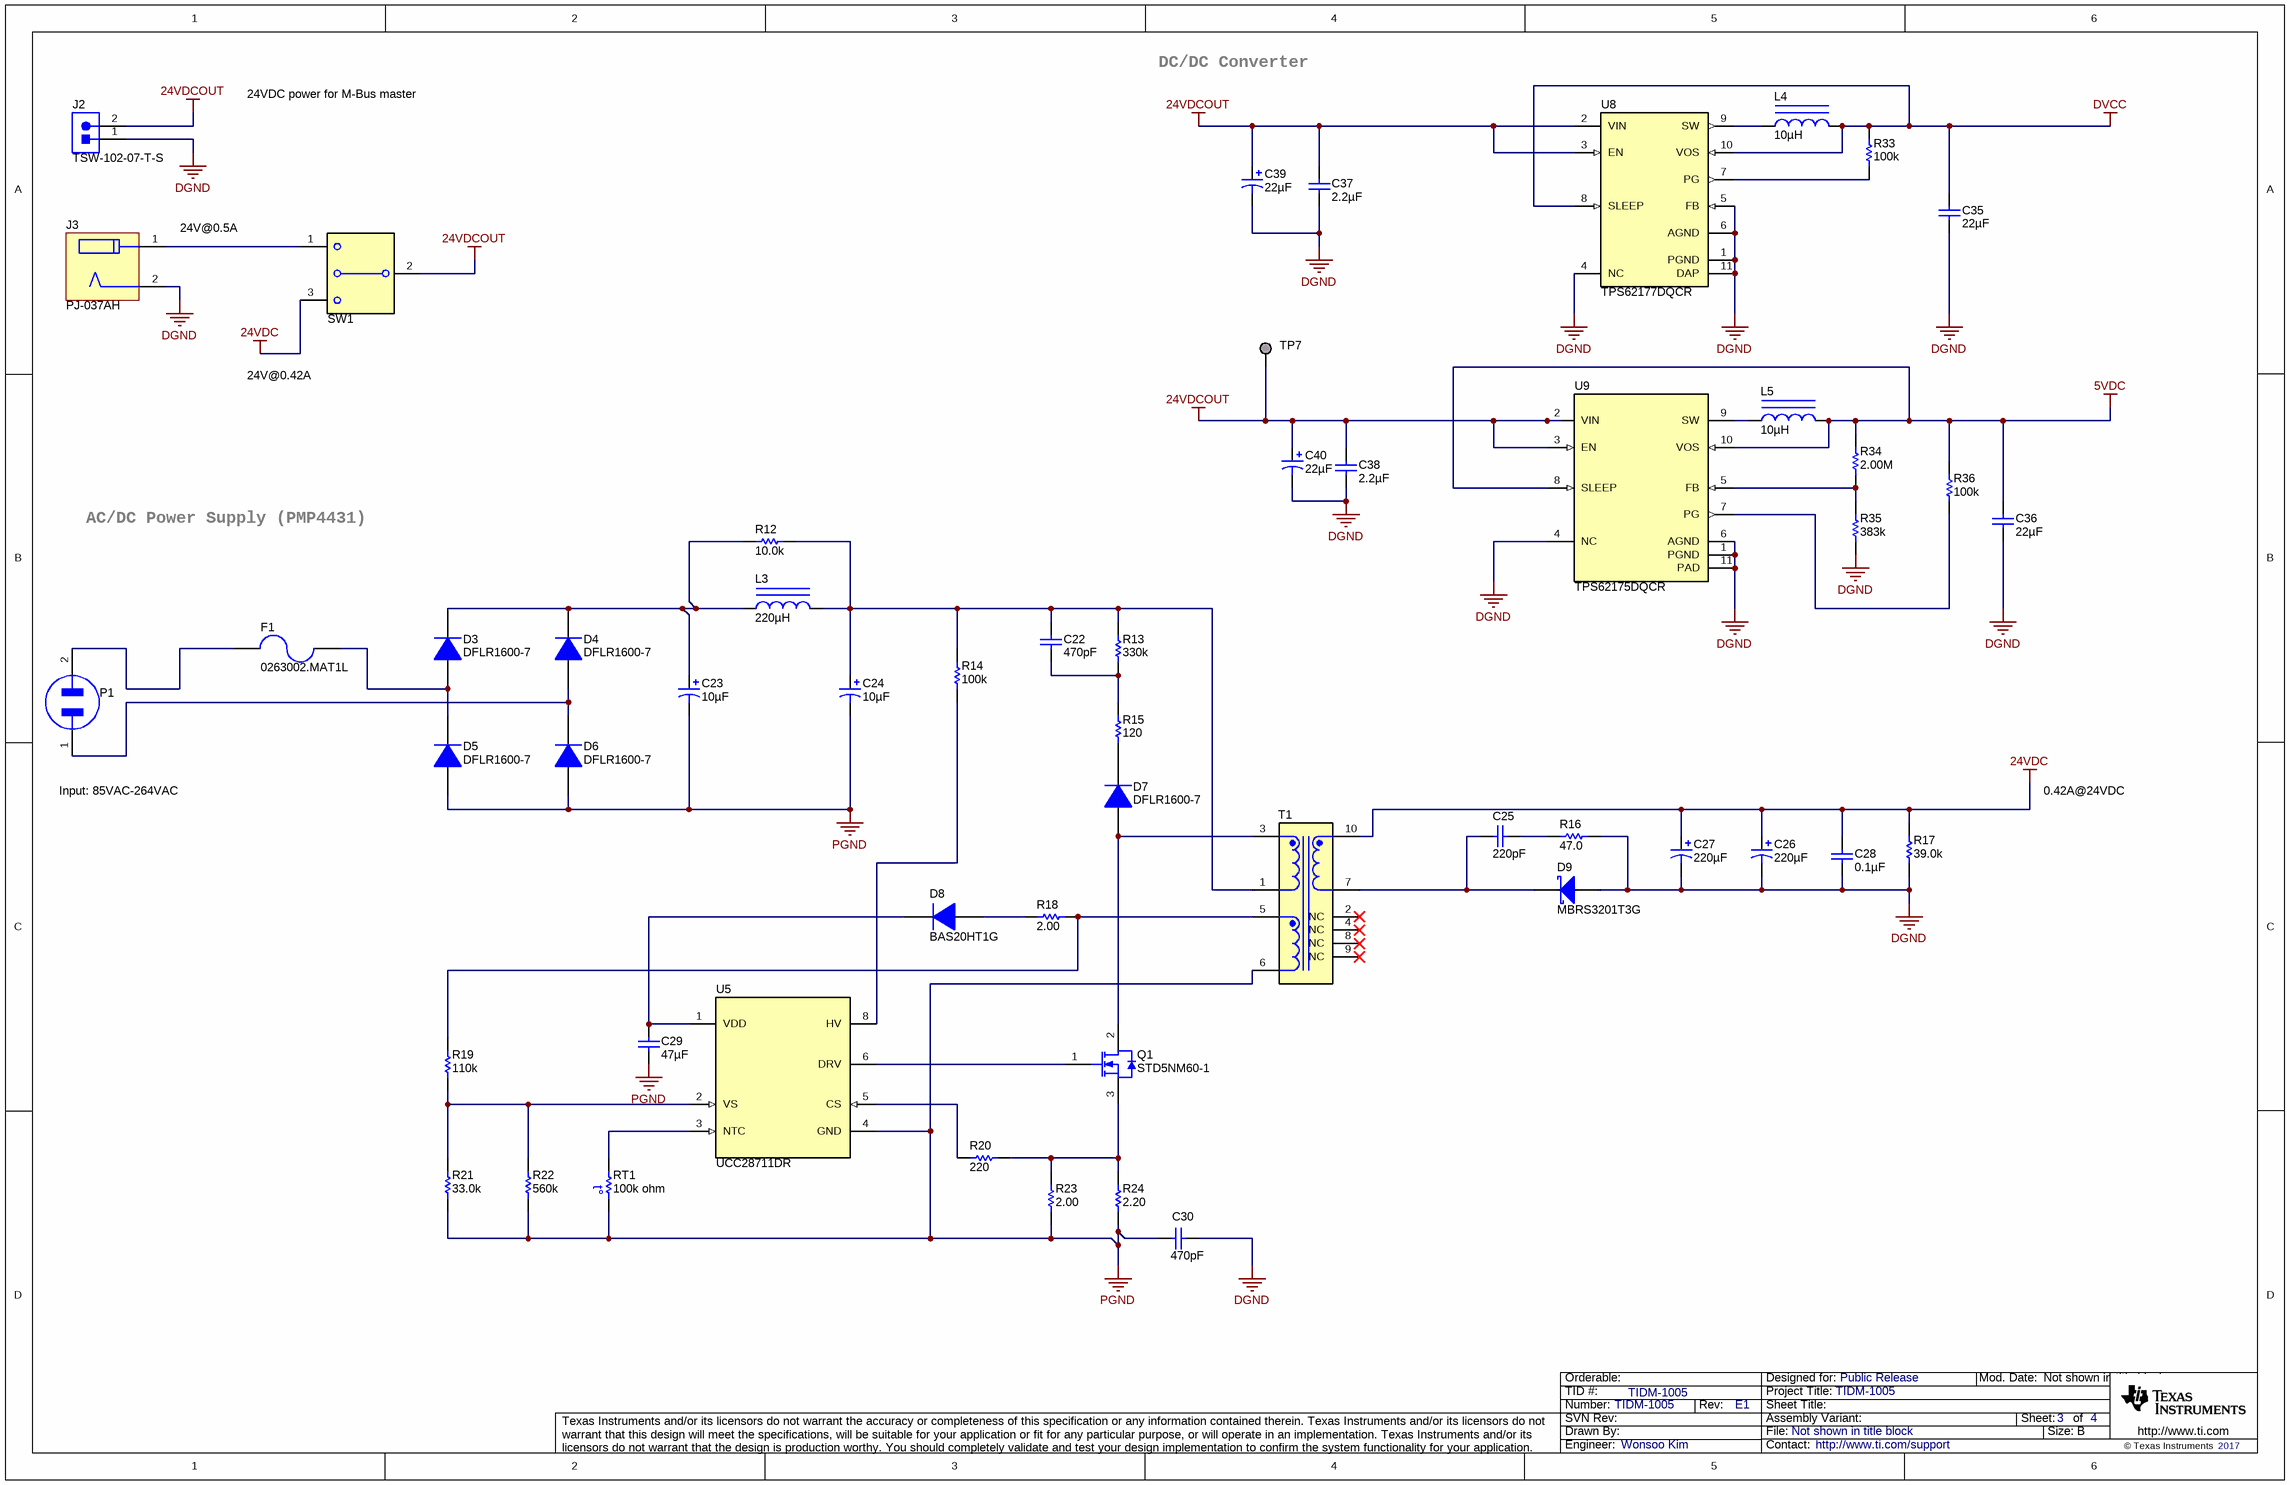
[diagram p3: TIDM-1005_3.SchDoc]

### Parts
C22  ValueDisplayed: 470pF  [1206]  (hidden comment: C3216C0G2J471J085AA)
C23  ValueDisplayed: 10µF  [CAPPRD500W60D1000H2000]  (hidden comment: UCS2G100MPD1TD)
C24  ValueDisplayed: 10µF  [CAPPRD500W60D1000H2000]  (hidden comment: UCS2G100MPD1TD)
C25  ValueDisplayed: 220pF  [0603]  (hidden comment: GRM188R72E221KW07D)
C26  ValueDisplayed: 220µF  [Nichicon_800x1500]  (hidden comment: UHE1V221MPD1TD)
C27  ValueDisplayed: 220µF  [Nichicon_800x1500]  (hidden comment: UHE1V221MPD1TD)
C28  ValueDisplayed: 0.1µF  [0603]  (hidden comment: 0603YC104JAT2A)
C29  ValueDisplayed: 47µF  [CKG57N]  (hidden comment: CKG57NX5R1E476M500JH)
C30  ValueDisplayed: 470pF  [VY2_750x500]  (hidden comment: VY2471K29Y5SS63V7)
C35  ValueDisplayed: 22µF  [0805_HV]  (hidden comment: GRM21BR60J226ME39L)
C36  ValueDisplayed: 22µF  [1206_180]  (hidden comment: GRM31CR61A226KE19L)
C37  ValueDisplayed: 2.2µF  [0805_HV]  (hidden comment: GRM21BR61E225KA12L)
C38  ValueDisplayed: 2.2µF  [0805_HV]  (hidden comment: GRM21BR61E225KA12L)
C39  ValueDisplayed: 22µF  [Panasonic_500x1100]  (hidden comment: ECA1HM220)
C40  ValueDisplayed: 22µF  [Panasonic_500x1100]  (hidden comment: ECA1HM220)
D3  DFLR1600-7  [PowerDI123]
D4  DFLR1600-7  [PowerDI123]
D5  DFLR1600-7  [PowerDI123]
D6  DFLR1600-7  [PowerDI123]
D7  DFLR1600-7  [PowerDI123]
D8  BAS20HT1G  [SOD-323]
D9  MBRS3201T3G  [SMC]
F1  0263002.MAT1L  [FUSE_263]
J2  TSW-102-07-T-S  [Samtec_TSW-102-07-T-S]
J3  PJ-037AH  [CUI_PJ-037AH]
L3  ValueDisplayed: 220µH  [WE-TI_5075]  (hidden comment: 7447462221)
L4  ValueDisplayed: 10µH  [LPS4018]  (hidden comment: LPS4018-103MRB)
L5  ValueDisplayed: 10µH  [LPS4018]  (hidden comment: LPS4018-103MRB)
P1  770W-X2/10  [CONN_AC_770W-SERIES]  (value not drawn)
Q1  STD5NM60-1  [IPAK]
R12  ValueDisplayed: 10.0k  [0805_HV]  (hidden comment: MCU08050C1002FP500)
R13  ValueDisplayed: 330k  [1206]  (hidden comment: RC1206FR-07330KL)
R14  ValueDisplayed: 100k  [0805_HV]  (hidden comment: MCU08050C1003FP500)
R15  ValueDisplayed: 120  [1206]  (hidden comment: RC1206FR-07120RL)
R16  ValueDisplayed: 47.0  [0805_HV]  (hidden comment: ERJ-P6WF47R0V)
R17  ValueDisplayed: 39.0k  [1206]  (hidden comment: ERJ-8ENF3902V)
R18  ValueDisplayed: 2.00  [0805_HV]  (hidden comment: RC0805FR-072RL)
R19  ValueDisplayed: 110k  [1206]  (hidden comment: RC1206FR-07110KL)
R20  ValueDisplayed: 220  [0603]  (hidden comment: MCT06030C2200FP500)
R21  ValueDisplayed: 33.0k  [0603]  (hidden comment: MCT06030C3302FP500)
R22  ValueDisplayed: 560k  [0603]  (hidden comment: CRCW0603560KFKEA)
R23  ValueDisplayed: 2.00  [0805_HV]  (hidden comment: RC0805FR-072RL)
R24  ValueDisplayed: 2.20  [0805_HV]  (hidden comment: RL1220S-2R2-F)
R33  ValueDisplayed: 100k  [0402]  (hidden comment: CRCW0402100KFKED)
R34  ValueDisplayed: 2.00M  [0402]  (hidden comment: CRCW04022M00FKED)
R35  ValueDisplayed: 383k  [0402]  (hidden comment: CRCW0402383KFKED)
R36  ValueDisplayed: 100k  [0402]  (hidden comment: CRCW0402100KFKED)
RT1  value 100k ohm  [0603]  (hidden comment: NCP18WF104F12RB)
SW1  100SP3T1B1M1QEH  [SW_100SP3T1B1M1QEH]  (value not drawn)
T1  RLTI-1223  [Renco_RLTI-1223]  (value not drawn)
TP7  TESTPOINT  [TESTPOINT]  (value not drawn)  (no BOM)
U5  UCC28711DR  [D0007A_N]
U8  TPS62177DQCR  [DQC0010A]
U9  TPS62175DQCR  [DQC0010A]

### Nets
5VDC: C36.1 L5.2 R34.1 R36.2 U9.8(SLEEP) U9.10(VOS)
24VDC: C26.1(+) C27.1(+) C28.1 R17.1 SW1.3 T1.10
24VDCOUT: C37.2 C38.2 C39.1(+) C40.1(+) J2.2 SW1.2(COM) TP7.1 U8.2(VIN) U8.3(EN) U9.2(VIN) U9.3(EN)
DGND: C26.2(-) C27.2(-) C28.2 C30.1 C35.2 C36.2 C37.1 C38.1 C39.2(-) C40.2(-) D9.2(A) J2.1 J3.2 R16.2 R17.2 R35.2 U8.1(PGND) U8.4(NC) U8.5(FB) U8.6(AGND) U8.11(DAP) U9.1(PGND) U9.4(NC) U9.6(AGND) U9.11(PAD)
DVCC: C35.1 L4.2 R33.2 U8.8(SLEEP) U8.10(VOS)
PGND: C23.2(-) C24.2(-) C29.1 C30.2 D5.2(A) D6.2(A) R21.2 R22.2 R23.2 R24.2 RT1.2 T1.6 U5.4(GND)
NetC22_1: C22.1 R13.2 R15.1
NetC22_2: C22.2 C24.1(+) L3.2 R12.2 R13.1 R14.1 T1.1
NetC23_1: C23.1(+) D3.1(K) D4.1(K) L3.1 R12.1
NetC25_1: C25.1 R16.1
NetC25_2: C25.2 D9.1(K) T1.7
NetC29_2: C29.2 D8.1(K) U5.1(VDD)
NetD3_2: D3.2(A) D5.1(K) F1.1
NetD4_2: D4.2(A) D6.1(K) P1.1(Neutral)
NetD7_1: D7.1(K) R15.2
NetD7_2: D7.2(A) Q1.2(D) T1.3
NetD8_2: D8.2(A) R18.1
NetF1_2: F1.2 P1.2(Hot)
NetJ3_1: J3.1 SW1.1
NetL4_1: L4.1 U8.9(SW)
NetL5_1: L5.1 U9.9(SW)
NetQ1_1: Q1.1(G) U5.6(DRV)
NetQ1_3: Q1.3(S) R20.2 R23.1 R24.1
NetR14_2: R14.2 U5.8(HV)
NetR18_2: R18.2 R19.1 T1.5
NetR19_2: R19.2 R21.1 R22.1 U5.2(VS)
NetR20_1: R20.1 U5.5(CS)
NetR33_1: R33.1 U8.7(PG)
NetR34_2: R34.2 R35.1 U9.5(FB)
NetR36_1: R36.1 U9.7(PG)
NetRT1_1: RT1.1 U5.3(NTC)

Not connected (* = marked no-connect by the designer): T1 2(NC)* 4(NC)* 8(NC)* 9(NC)*

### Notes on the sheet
- DC/DC Converter
- 24VDC power for M-Bus master
- 24V@0.5A
- 24V@0.42A
- AC/DC Power Supply (PMP4431)
- Input: 85VAC-264VAC
- 0.42A@24VDC

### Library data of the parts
C22 = C3216C0G2J471J085AA: CAP, CERM, 470 pF, 630 V, +/- 5%, C0G/NP0, 1206; Manufacturer: TDK; Polarized: N; CompType: Capacitor; Value: 470pF; U/M: EA; Cap_F: 0.00000000047; Tolerance_%: 5; Value1: Unknown; VDC_V: 630; Value2: 630V; TaMin_C: -55; TaMax_C: 125; SizeArea_mm2: 5.12; SizeAreaWB_mm2: 10.92; SizeX_mm: 3.2; SizeY_mm: 1.6; SizeZ_mm: 1.35; AEC Category: Q200
C23 C24 = UCS2G100MPD1TD: CAP, AL, 10 µF, 400 V, +/- 20%, TH; Manufacturer: Nichicon; Polarized: Y; CompType: Capacitor; Value: 10uF; U/M: EA; Cap_F: 0.00001; Tolerance_%: 20; Value1: Unknown; VDC_V: 400; Value2: 400V; IRMS_A: 0.35; TaMin_C: -40; TaMax_C: 105; SizeAreaWB_mm2: 144; SizeArea_mm2: 100; SizeX_mm: 10; SizeZ_mm: 22; AEC Category: Q200; AEC Qualified: N
C25 = GRM188R72E221KW07D: CAP, CERM, 220 pF, 250 V, +/- 10%, X7R, 0603; Manufacturer: MuRata; Polarized: N; CompType: Capacitor; Value: 220pF; U/M: EA; Cap_F: 0.00000000022; Tolerance_%: 10; Value1: Unknown; VDC_V: 250; Value2: 250V; TaMin_C: -55; TaMax_C: 125; SizeArea_mm2: 1.28; SizeAreaWB_mm2: 4.68; SizeX_mm: 1.6; SizeY_mm: 0.8; SizeZ_mm: 1; AEC Category: Q200
C26 C27 = UHE1V221MPD1TD: CAP, AL, 220 µF, 35 V, +/- 20%, TH; Manufacturer: Nichicon; Polarized: Y; CompType: Capacitor; Value: 220uF; U/M: EA; Cap_F: 0.00022; Tolerance_%: 20; Value1: Unknown; VDC_V: 35; Value2: 35V; IRMS_A: 0.84; TaMin_C: -40; TaMax_C: 105; Cap_Case: 8x15; SizeAreaWB_mm2: 100; SizeArea_mm2: 64; SizeX_mm: 8; SizeZ_mm: 16.5; AEC Category: Q200; AEC Qualified: N
C28 = 0603YC104JAT2A: CAP, CERM, 0.1 µF, 16 V, +/- 5%, X7R, 0603; Manufacturer: AVX; Polarized: N; CompType: Capacitor; Value: 0.1uF; U/M: EA; Cap_F: 0.0000001; Tolerance_%: 5; ESR_ohm: 0.039; Value1: 0.039 ohm; VDC_V: 16; Value2: 16V; TaMin_C: -55; TaMax_C: 125; SizeArea_mm2: 1.28; SizeAreaWB_mm2: 4.68; SizeX_mm: 1.6; SizeY_mm: 0.8; SizeZ_mm: 1; AEC Category: Q200
C29 = CKG57NX5R1E476M500JH: CAP, CERM, 47 µF, 25 V, +/- 20%, X5R, 6x5x5mm; Manufacturer: TDK; Polarized: N; CompType: Capacitor; Value: 47uF; U/M: EA; Cap_F: 0.000047; Tolerance_%: 20; Value1: Unknown; VDC_V: 25; Value2: 25V; TaMin_C: -55; TaMax_C: 85; Cap_Case: 2220; SizeArea_mm2: 30; SizeAreaWB_mm2: 56; SizeX_mm: 6; SizeY_mm: 5; SizeZ_mm: 5.5; AEC Category: Q200
C30 = VY2471K29Y5SS63V7: CAP, CERM, 470 pF, 300 V, +/- 10%, VY2, 5x7.5 mm; Manufacturer: Vishay-Bccomponents; Polarized: N; CompType: Capacitor; Value: 470pF; U/M: EA; Cap_F: 0.00000000047; Tolerance_%: 10; Value1: Unknown; VDC_V: 300; Value2: 300V; TaMin_C: -40; TaMax_C: 125; Cap_Case: Disk, 5x7.5 mm; SizeArea_mm2: 37.5; SizeAreaWB_mm2: 66.5; SizeX_mm: 7.5; SizeY_mm: 5; SizeZ_mm: 10.5; AEC Category: Q200
C35 = GRM21BR60J226ME39L: CAP, CERM, 22 µF, 6.3 V, +/- 20%, X5R, 0805; Manufacturer: MuRata; Polarized: N; CompType: Capacitor; Value: 22uF; U/M: EA; Cap_F: 0.000022; Tolerance_%: 20; ESR_ohm: 0.009; Value1: 0.009 ohm; VDC_V: 6.3; Value2: 6.3V; IRMS_A: 3.5; TaMin_C: -55; TaMax_C: 85; Cap_Case: 0805; SizeArea_mm2: 2.5; SizeAreaWB_mm2: 6.75; SizeX_mm: 2; SizeY_mm: 1.25; SizeZ_mm: 1.45; AEC Category: Q200
C36 = GRM31CR61A226KE19L: CAP, CERM, 22 µF, 10 V, +/- 10%, X5R, 1206; Manufacturer: MuRata; Polarized: N; CompType: Capacitor; Value: 22uF; U/M: EA; Cap_F: 0.000022; Tolerance_%: 10; Value1: Unknown; Value2: 10V; TaMin_C: -55; TaMax_C: 85; Cap_Case: 1206; SizeArea_mm2: 5.12; SizeAreaWB_mm2: 10.92; SizeX_mm: 3.2; SizeY_mm: 1.6; SizeZ_mm: 1.8; AEC Category: Q200
C37 C38 = GRM21BR61E225KA12L: CAP, CERM, 2.2 µF, 25 V, +/- 10%, X5R, 0805; Manufacturer: MuRata; Polarized: N; CompType: Capacitor; Value: 2.2uF; U/M: EA; Cap_F: 0.0000022; Tolerance_%: 10; ESR_ohm: 0.008; Value1: 0.008 ohm; VDC_V: 25; Value2: 25V; TaMin_C: -55; TaMax_C: 85; Cap_Case: 0805; SizeArea_mm2: 2.5; SizeAreaWB_mm2: 6.75; SizeX_mm: 2; SizeY_mm: 1.25; SizeZ_mm: 1.45; AEC Category: Q200
C39 C40 = ECA1HM220: CAP, AL, 22 µF, 50 V, +/- 20%, TH; Manufacturer: Panasonic; Polarized: Y; CompType: Capacitor; Value: 22uF; U/M: EA; Cap_F: 0.000022; Tolerance_%: 20; Value1: Unknown; VDC_V: 50; Value2: 50V; TaMin_C: -40; TaMax_C: 85; Cap_Case: 5x11; SizeAreaWB_mm2: 49; SizeArea_mm2: 25; SizeX_mm: 5; SizeZ_mm: 12.5; AEC Category: Q200; AEC Qualified: N
D3-D7 = DFLR1600-7: Diode, Standard Recovery Rectifier, 600 V, 1 A, PowerDI123; Manufacturer: Diodes Inc.; U/M: EA; Vf_V: 1.1; Value: 600V; Value1: 1A; Value2: 1.1V; Io_A: 1; Vr_V: 600; TJmax_C: 150; SizeAreaWB_mm2: 13.066; SizeArea_mm2: 6.586; SizeX_mm: 3.7; SizeY_mm: 1.78; SizeZ_mm: 0.98; AEC Category: Q101
D8 = BAS20HT1G: Diode, Switching, 200 V, 0.2 A, AEC-Q101, SOD-323; Manufacturer: ON Semiconductor; U/M: EA; Vf_V: 1.25; Value: 200V; Value1: 0.2A; Value2: 1.25V; Io_A: 0.2; Vr_V: 200; TJmax_C: 150; SizeAreaWB_mm2: 8.695; SizeArea_mm2: 3.645; SizeX_mm: 2.7; SizeY_mm: 1.35; SizeZ_mm: 1; AEC Category: Q101; AEC Qualified: Y
D9 = MBRS3201T3G: Diode, Schottky, 200 V, 3 A, SMC; Manufacturer: ON Semiconductor; U/M: EA; Vf_V: 0.84; Value: 200V; Value1: 3A; Value2: 0.84V; Io_A: 3; Vr_V: 200; TJmax_C: 150; SizeAreaWB_mm2: 83.2686; SizeArea_mm2: 50.5686; SizeX_mm: 8.13; SizeY_mm: 6.22; SizeZ_mm: 2.6; AEC Category: Q101; AEC Qualified: N
F1 = 0263002.MAT1L: Fuse, 2 A, 250 VAC, TH; Manufacturer: Littelfuse; VAC_V: 250; Interrupt_AC: 50; Irating_A: 2; Rtyp_Ohm: 0.0444; MeltingTyp: 0.74
J2 = TSW-102-07-T-S: as GPIO1 on sheet TIDM-1005_1
J3 = PJ-037AH: Power Jack, 2mm, R/A, TH; Manufacturer: CUI Inc.; SymbolCreator: Altium; Pitch_mm: 6; Gender: Male; Shrouded: N; Row_Count: 1
L3 = 7447462221: Inductor, Unshielded Drum Core, Ferrite, 220 µH, 0.5 A, 0.96 ohm, TH; Manufacturer: Wurth Elektronik; Value: 220uH; Ind_H: 220.0E-6; Imax_A: 0.5; Irms: 0.5A @ 40C rise; Isat: 0.5A @ 10% inductance drop; DCR_ohm: 0.96; Value2: 0.5A; SizeAreaWB_mm2: 64; SizeArea_mm2: 36; SizeX_mm: 6; SizeZ_mm: 8.5; AEC Category: Q200
L4 L5 = LPS4018-103MRB: Inductor, Shielded Drum Core, Ferrite, 10 µH, 1.25 A, 0.18 ohm, SMD; Manufacturer: Coilcraft; Value: 10uH; Ind_H: 10.0E-6; Imax_A: 1.25; Irms: 1.25A @ 40C rise; Isat: 1.3A @ 30% inductance drop; DCR_ohm: 0.18; Value2: 1.25A; SizeAreaWB_mm2: 24.01; SizeArea_mm2: 15.21; SizeX_mm: 3.9; SizeZ_mm: 1.7; AEC Category: Q200; AEC Qualified: N
P1 = 770W-X2/10: AC Receptacle, 2.5A, R/A, TH; Manufacturer: Qualtek Electronics Corporation; SymbolCreator: a0412235
Q1 = STD5NM60-1: MOSFET, N-CH, 650 V, 5 A, IPAK; Manufacturer: STMicroelectronics; Alternate Manufacturer: None; U/M: EA; ChType: N; Value: 650V; VdsMax_V: 650; Value1: ? ohm; Value2: 13 nC; QgTyp_nC: 13; Vgs_V: 30; IdsMax_A: 5; SizeAreaWB_mm2: 36.5512; SizeArea_mm2: 14.9112; SizeX_mm: 6.54; SizeY_mm: 2.28; SizeZ_mm: 9.78; AEC Category: Q101
R12 = MCU08050C1002FP500: RES, 10.0 k, 1%, 0.2 W, 0805; Manufacturer: Vishay/Beyschlag; CompType: Resistor; Value: 10.0k; Res_ohm: 10000; Value_Code: 10k0; Tolerance_%: 1; Power_W: 0.2; Value2: 0.2W; VDC_V: 150; TempCo: 50 ppm/C; SizeArea_mm2: 2.5; SizeX_mm: 2; SizeY_mm: 1.25; SizeZ_mm: 1.45; EIA_Code: E96; U/M: EA; AEC Category: Q200; AEC Qualified: N
R13 = RC1206FR-07330KL: RES, 330 k, 1%, 0.25 W, 1206; Manufacturer: Yageo America; CompType: Resistor; Value: 330k; Res_ohm: 330000; Tolerance_%: 1; Power_W: 0.25; Value2: 0.25W; VDC_V: 200; TempCo: 100 ppm/C; SizeArea_mm2: 5.12; SizeX_mm: 3.2; SizeY_mm: 1.6; SizeZ_mm: 1.35; U/M: EA; AEC Category: Q200
R14 = MCU08050C1003FP500: RES, 100 k, 1%, 0.2 W, 0805; Manufacturer: Vishay/Beyschlag; CompType: Resistor; Value: 100k; Res_ohm: 100000; Tolerance_%: 1; Power_W: 0.2; Value2: 0.2W; VDC_V: 150; TempCo: 50 ppm/C; SizeArea_mm2: 2.5; SizeX_mm: 2; SizeY_mm: 1.25; SizeZ_mm: 1.45; EIA_Code: E96; U/M: EA; AEC Category: Q200; AEC Qualified: N
R15 = RC1206FR-07120RL: RES, 120, 1%, 0.25 W, 1206; Manufacturer: Yageo America; CompType: Resistor; Value: 120; Value_Code: 120R; Tolerance_%: 1; Power_W: 0.25; Value2: 0.25W; VDC_V: 200; TempCo: 100 ppm/C; SizeArea_mm2: 5.12; SizeX_mm: 3.2; SizeY_mm: 1.6; SizeZ_mm: 1.35; U/M: EA; AEC Category: Q200
R16 = ERJ-P6WF47R0V: RES, 47.0, 1%, 0.5 W, AEC-Q200 Grade 0, 0805; Manufacturer: Panasonic; CompType: Resistor; Value: 47.0; Res_ohm: 47; Value_Code: 47R0; Tolerance_%: 1; Power_W: 0.5; Value2: 0.5W; TempCo: 200 ppm/C; SizeArea_mm2: 2.5; SizeX_mm: 2; SizeY_mm: 1.25; SizeZ_mm: 1.45; U/M: EA; AEC Category: Q200; AEC Qualified: Y; AEC Grade: 0
R17 = ERJ-8ENF3902V: RES, 39.0 k, 1%, 0.25 W, AEC-Q200 Grade 0, 1206; Manufacturer: Panasonic; CompType: Resistor; Value: 39.0k; Res_ohm: 39000; Value_Code: 39k0; Tolerance_%: 1; Power_W: 0.25; Value2: 0.25W; VDC_V: 200; TempCo: 100 ppm/C; SizeArea_mm2: 5.12; SizeX_mm: 3.2; SizeY_mm: 1.6; SizeZ_mm: 1.35; U/M: EA; AEC Category: Q200; AEC Qualified: Y; AEC Grade: 0
R18 R23 = RC0805FR-072RL: RES, 2.00, 1%, 0.125 W, 0805; Manufacturer: Yageo America; CompType: Resistor; Value: 2.00; Res_ohm: 2; Value_Code: 2R00; Tolerance_%: 1; Power_W: 0.125; Value2: 0.125W; VDC_V: 150; TempCo: 200 ppm/C; SizeArea_mm2: 2.5; SizeY_mm: 1.25; SizeZ_mm: 1.45; EIA_Code: E96; U/M: EA; AEC Category: Q200
R19 = RC1206FR-07110KL: RES, 110 k, 1%, 0.25 W, 1206; Manufacturer: Yageo America; CompType: Resistor; Value: 110k; Res_ohm: 110000; Tolerance_%: 1; Power_W: 0.25; Value2: 0.25W; VDC_V: 200; TempCo: 100 ppm/C; SizeArea_mm2: 5.12; SizeX_mm: 3.2; SizeY_mm: 1.6; SizeZ_mm: 1.35; EIA_Code: E96; U/M: EA; AEC Category: Q200
R20 = MCT06030C2200FP500: RES, 220, 1%, 0.125 W, 0603; Manufacturer: Vishay/Beyschlag; CompType: Resistor; Value: 220; Value_Code: 220R; Tolerance_%: 1; Power_W: 0.125; Value2: 0.125W; VDC_V: 75; TempCo: 50 ppm/C; SizeArea_mm2: 1.28; SizeX_mm: 1.6; SizeY_mm: 0.8; U/M: EA; AEC Category: Q200; AEC Qualified: N
R21 = MCT06030C3302FP500: RES, 33.0 k, 1%, 0.125 W, 0603; Manufacturer: Vishay/Beyschlag; CompType: Resistor; Value: 33.0k; Res_ohm: 33000; Value_Code: 33k0; Tolerance_%: 1; Power_W: 0.125; Value2: 0.125W; VDC_V: 75; TempCo: 50 ppm/C; SizeArea_mm2: 1.28; SizeX_mm: 1.6; SizeY_mm: 0.8; U/M: EA; AEC Category: Q200; AEC Qualified: N
R22 = CRCW0603560KFKEA: RES, 560 k, 1%, 0.1 W, AEC-Q200 Grade 0, 0603; Manufacturer: Vishay-Dale; CompType: Resistor; Value: 560k; Res_ohm: 560000; Tolerance_%: 1; Power_W: 0.1; Value2: 0.1W; VDC_V: 75; TempCo: 100 ppm/C; SizeArea_mm2: 1.28; SizeX_mm: 1.6; SizeY_mm: 0.8; U/M: EA; AEC Category: Q200; AEC Qualified: Y; AEC Grade: 0
R24 = RL1220S-2R2-F: RES, 2.20, 1%, 0.333 W, 0805; Manufacturer: Susumu Co Ltd; CompType: Resistor; Value: 2.20; Res_ohm: 2.2; Value_Code: 2R20; Tolerance_%: 1; Power_W: 0.333; Value2: 0.333W; TempCo: 200 ppm/C; SizeArea_mm2: 2.5; SizeX_mm: 2; SizeY_mm: 1.25; SizeZ_mm: 1.45; U/M: EA; AEC Category: Q200; AEC Qualified: N
R33 R36 = CRCW0402100KFKED: RES, 100 k, 1%, 0.063 W, 0402; Manufacturer: Vishay-Dale; CompType: Resistor; Value: 100k; Res_ohm: 100000; Tolerance_%: 1; Power_W: 0.063; Value2: 0.063W; VDC_V: 50; TempCo: 100 ppm/C; SizeArea_mm2: 0.5; SizeZ_mm: 0.6; EIA_Code: E96; U/M: EA; AEC Category: Q200
R34 = CRCW04022M00FKED: RES, 2.00 M, 1%, 0.063 W, 0402; Manufacturer: Vishay-Dale; CompType: Resistor; Value: 2.00Meg; Res_ohm: 2000000; Value_Code: 2M00; Tolerance_%: 1; Power_W: 0.063; Value2: 0.063W; VDC_V: 50; TempCo: 100 ppm/C; SizeArea_mm2: 0.5; SizeZ_mm: 0.6; EIA_Code: E96; U/M: EA; AEC Category: Q200
R35 = CRCW0402383KFKED: RES, 383 k, 1%, 0.063 W, 0402; Manufacturer: Vishay-Dale; CompType: Resistor; Value: 383k; Res_ohm: 383000; Tolerance_%: 1; Power_W: 0.063; Value2: 0.063W; VDC_V: 50; TempCo: 100 ppm/C; SizeArea_mm2: 0.5; SizeZ_mm: 0.6; EIA_Code: E96; U/M: EA; AEC Category: Q200
RT1 = NCP18WF104F12RB: Thermistor NTC, 100k ohm, 1%, 0603; Manufacturer: MuRata; Tolerance_%: 1; Power_W: 0.1; TaMin_C: -40; TaMax_C: 125; SizeAreaWB_mm2: 4.68; SizeArea_mm2: 1.28; SizeX_mm: 1.6; SizeY_mm: 0.8; U/M: EA
SW1 = 100SP3T1B1M1QEH: Switch, Toggle SPDT 5A, 120V, TH; Manufacturer: E-Switch; SymbolCreator: a0799628; VDC_V: 28; SwitchFunction: ON-OFF-ON; PositionCount: 3; CurrentRating_mA: 5000
T1 = RLTI-1223: Transformer, 720 uH, TH; Manufacturer: Renco Electronics; SymbolCreator: Altium; Lp: 720; DCR_ohm: 1.65; Rs1: 0.23; Rs2: 0.225; SizeAreaWB_mm2: 393.27659; SizeArea_mm2: 317.90259; SizeX_mm: 17.145; SizeY_mm: 18.542; SizeZ_mm: 22.68
TP7 = TESTPOINT: TEST POINT.  No entry in BOM.
U5 = UCC28711DR: Constant-Voltage, Constant-Current Controller With Primary-Side Regulation, D0007A (SOIC-7); Manufacturer: Texas Instruments; SymbolCreator: Altium; SizeArea_mm2: 29.4; SizeAreaWB_mm2: 55.2; SizeX_mm: 6; SizeY_mm: 4.9; SizeZ_mm: 1.75; CompType: IC; U/M: EA
U8 = TPS62177DQCR: 28V, 0.5A Step-Down Converter with SNOOZE Mode, DQC0010A (WSON-10); Alternate PartNumber: TPS62177DQCT; Manufacturer: Texas Instruments; SymbolCreator: a0799628; SizeArea_mm2: 6; SizeAreaWB_mm2: 12; SizeX_mm: 2; SizeY_mm: 3; SizeZ_mm: 0.8; CompType: IC; U/M: EA
U9 = TPS62175DQCR: 28V, 0.5A Step-Down Converter with SNOOZE Mode, DQC0010A (WSON-10); Alternate PartNumber: TPS62175DQCT; Manufacturer: Texas Instruments; SymbolCreator: a0411947; SizeArea_mm2: 6; SizeAreaWB_mm2: 12; SizeX_mm: 2; SizeY_mm: 3; SizeZ_mm: 0.8; CompType: IC; U/M: EA

## Sheet TIDM-1005-EVM_Hardware.SchDoc
size 431 x 279 mm; Date: Not shown in title block; ApprovedBy: Not shown in title block; CheckedBy: Not shown in title block; Author: Not shown in title block; CompanyName: Not shown in title block; Engineer: Not shown in title block; Organization: Not shown in title block; Address1: Not shown in title block; Address2: Not shown in title block; Address3: Not shown in title block; Address4: Not shown in title block; DocumentNumber: 1; Revision: Use project parameter SCH_Rev; SheetNumber: 4; SheetTotal: 4; PageSetup: Record=PageOptions¦CenterHorizontal=True¦CenterVertical=True¦PrintScale=1.00¦XCorrection=1.00¦YCorrection=1.00¦PrintKind=0¦BorderSize=5000000¦LeftOffset=0¦BottomOffset=0¦Orientation=2¦PaperLength=1000¦PaperWidth=1000¦Scale=100¦PaperSource=15¦PrintQuality=600¦MediaType=1¦DitherType=10¦PaperKind=Letter¦PrintScaleMode=1
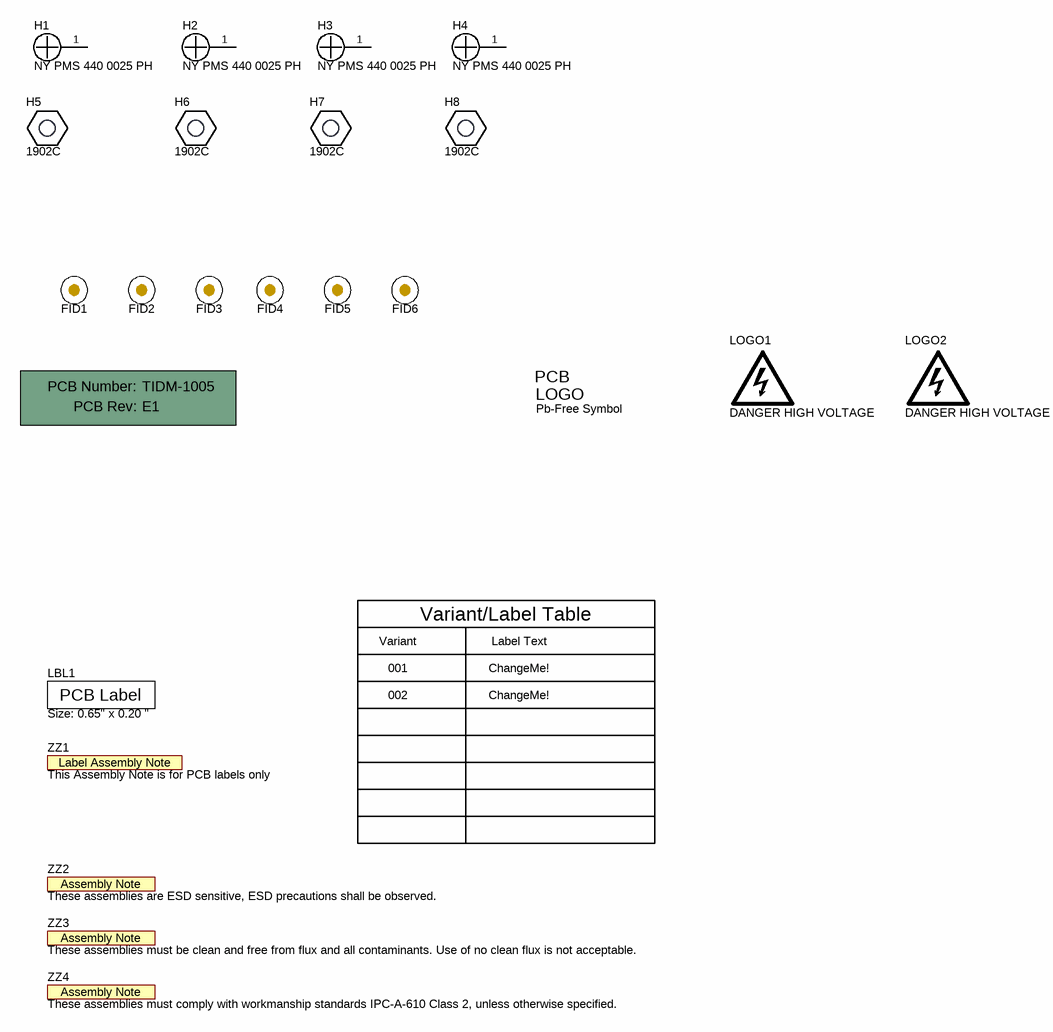
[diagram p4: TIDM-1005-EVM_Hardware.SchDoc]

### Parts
!PCB1  Printed Circuit Board  (value not drawn)  (mechanical)
FID1  Fiducial  [Fiducial10-20]  (value not drawn)
FID2  Fiducial  [Fiducial10-20]  (value not drawn)
FID3  Fiducial  [Fiducial10-20]  (value not drawn)
FID4  Fiducial  [Fiducial10-20]  (value not drawn)
FID5  Fiducial  [Fiducial10-20]  (value not drawn)
FID6  Fiducial  [Fiducial10-20]  (value not drawn)
H1  NY PMS 440 0025 PH  [NY PMS 440 0025 PH]
H2  NY PMS 440 0025 PH  [NY PMS 440 0025 PH]
H3  NY PMS 440 0025 PH  [NY PMS 440 0025 PH]
H4  NY PMS 440 0025 PH  [NY PMS 440 0025 PH]
H5  1902C  [Keystone_1902C]
H6  1902C  [Keystone_1902C]
H7  1902C  [Keystone_1902C]
H8  1902C  [Keystone_1902C]
LBL1  Size: 0.65" x 0.20 "  [Label_650x200]
LOGO1  DANGER HIGH VOLTAGE  [IEC_HighVoltage_Medium]  (no BOM)
LOGO2  DANGER HIGH VOLTAGE  [IEC_HighVoltage_Medium]  (no BOM)
Logo4  Pb-Free Symbol  [Pb-Free_Overlay_Small]  (no BOM)
ZZ1  This Assembly Note is for PCB labels only  [AssemblyNoteLabel]  (no BOM)
ZZ2  These assemblies are ESD sensitive, ESD precautions shall be observed.  [AssemblyNote]  (no BOM)
ZZ3  These assemblies must be clean and free from flux and all contaminants. Use of no clean flux is not acceptable.  [AssemblyNote]  (no BOM)
ZZ4  These assemblies must comply with workmanship standards IPC-A-610 Class 2, unless otherwise specified.  [AssemblyNote]  (no BOM)

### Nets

Not connected (* = marked no-connect by the designer): H1 1; H2 1; H3 1; H4 1

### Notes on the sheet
- Variant
- Variant/Label Table
- Label Text
- 001
- 002
- ChangeMe!

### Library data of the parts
!PCB1 = PCB: Manufacturer: Any; SymbolCreator: a0412235
FID1-FID6 = Fiducial: Fiducial mark.  There is nothing to buy or mount.; SymbolCreator: codlsc
H1-H4 = NY PMS 440 0025 PH: Machine Screw, Round, #4-40 x 1/4, Nylon, Philips panhead; Manufacturer: B&F Fastener Supply; CompType: Hardware; SymbolCreator: codlsc; U/M: EA
H5-H8 = 1902C: Standoff, Hex, 0.5"L #4-40 Nylon; Manufacturer: Keystone; CompType: Hardware
LBL1 = THT-14-423-10: Thermal Transfer Printable Labels, 0.650" W x 0.200" H - 10,000 per roll; Manufacturer: Brady; SymbolCreator: a0412235; CompType: Label
LOGO1 LOGO2 = IEC_HighVoltage: IEC 61010-1 High Voltage Warning; SymbolCreator: a0412235
Logo4 = Pb-Free: SymbolCreator: a0412235
ZZ1 = AssemblyNoteLabel: SymbolCreator: a0412235
ZZ2-ZZ4 = AssemblyNote: SymbolCreator: codlsc

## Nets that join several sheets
5VDC: TIDM-1005_2 (7 pins), TIDM-1005_3 (6 pins)
DGND: TIDM-1005_1 (27 pins), TIDM-1005_2 (14 pins), TIDM-1005_3 (25 pins)
DVCC: TIDM-1005_1 (16 pins), TIDM-1005_2 (8 pins), TIDM-1005_3 (5 pins)
I2C_SCL: TIDM-1005_1 (U1.39), TIDM-1005_2 (R96.2)
I2C_SDA: TIDM-1005_1 (U1.38), TIDM-1005_2 (R97.2)
INTERRUPT: TIDM-1005_1 (U1.46), TIDM-1005_2 (R92.2)
RS485_EN: TIDM-1005_1 (U1.33), TIDM-1005_2 (U11.2)
RS485_RXD: TIDM-1005_1 (U1.34), TIDM-1005_2 (U12.4)
RS485_TXD: TIDM-1005_1 (U1.35), TIDM-1005_2 (U10.2)
RST_POR: TIDM-1005_1 (R31.1), TIDM-1005_2 (R32.1 U6.1)

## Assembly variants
001: not fitted R31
